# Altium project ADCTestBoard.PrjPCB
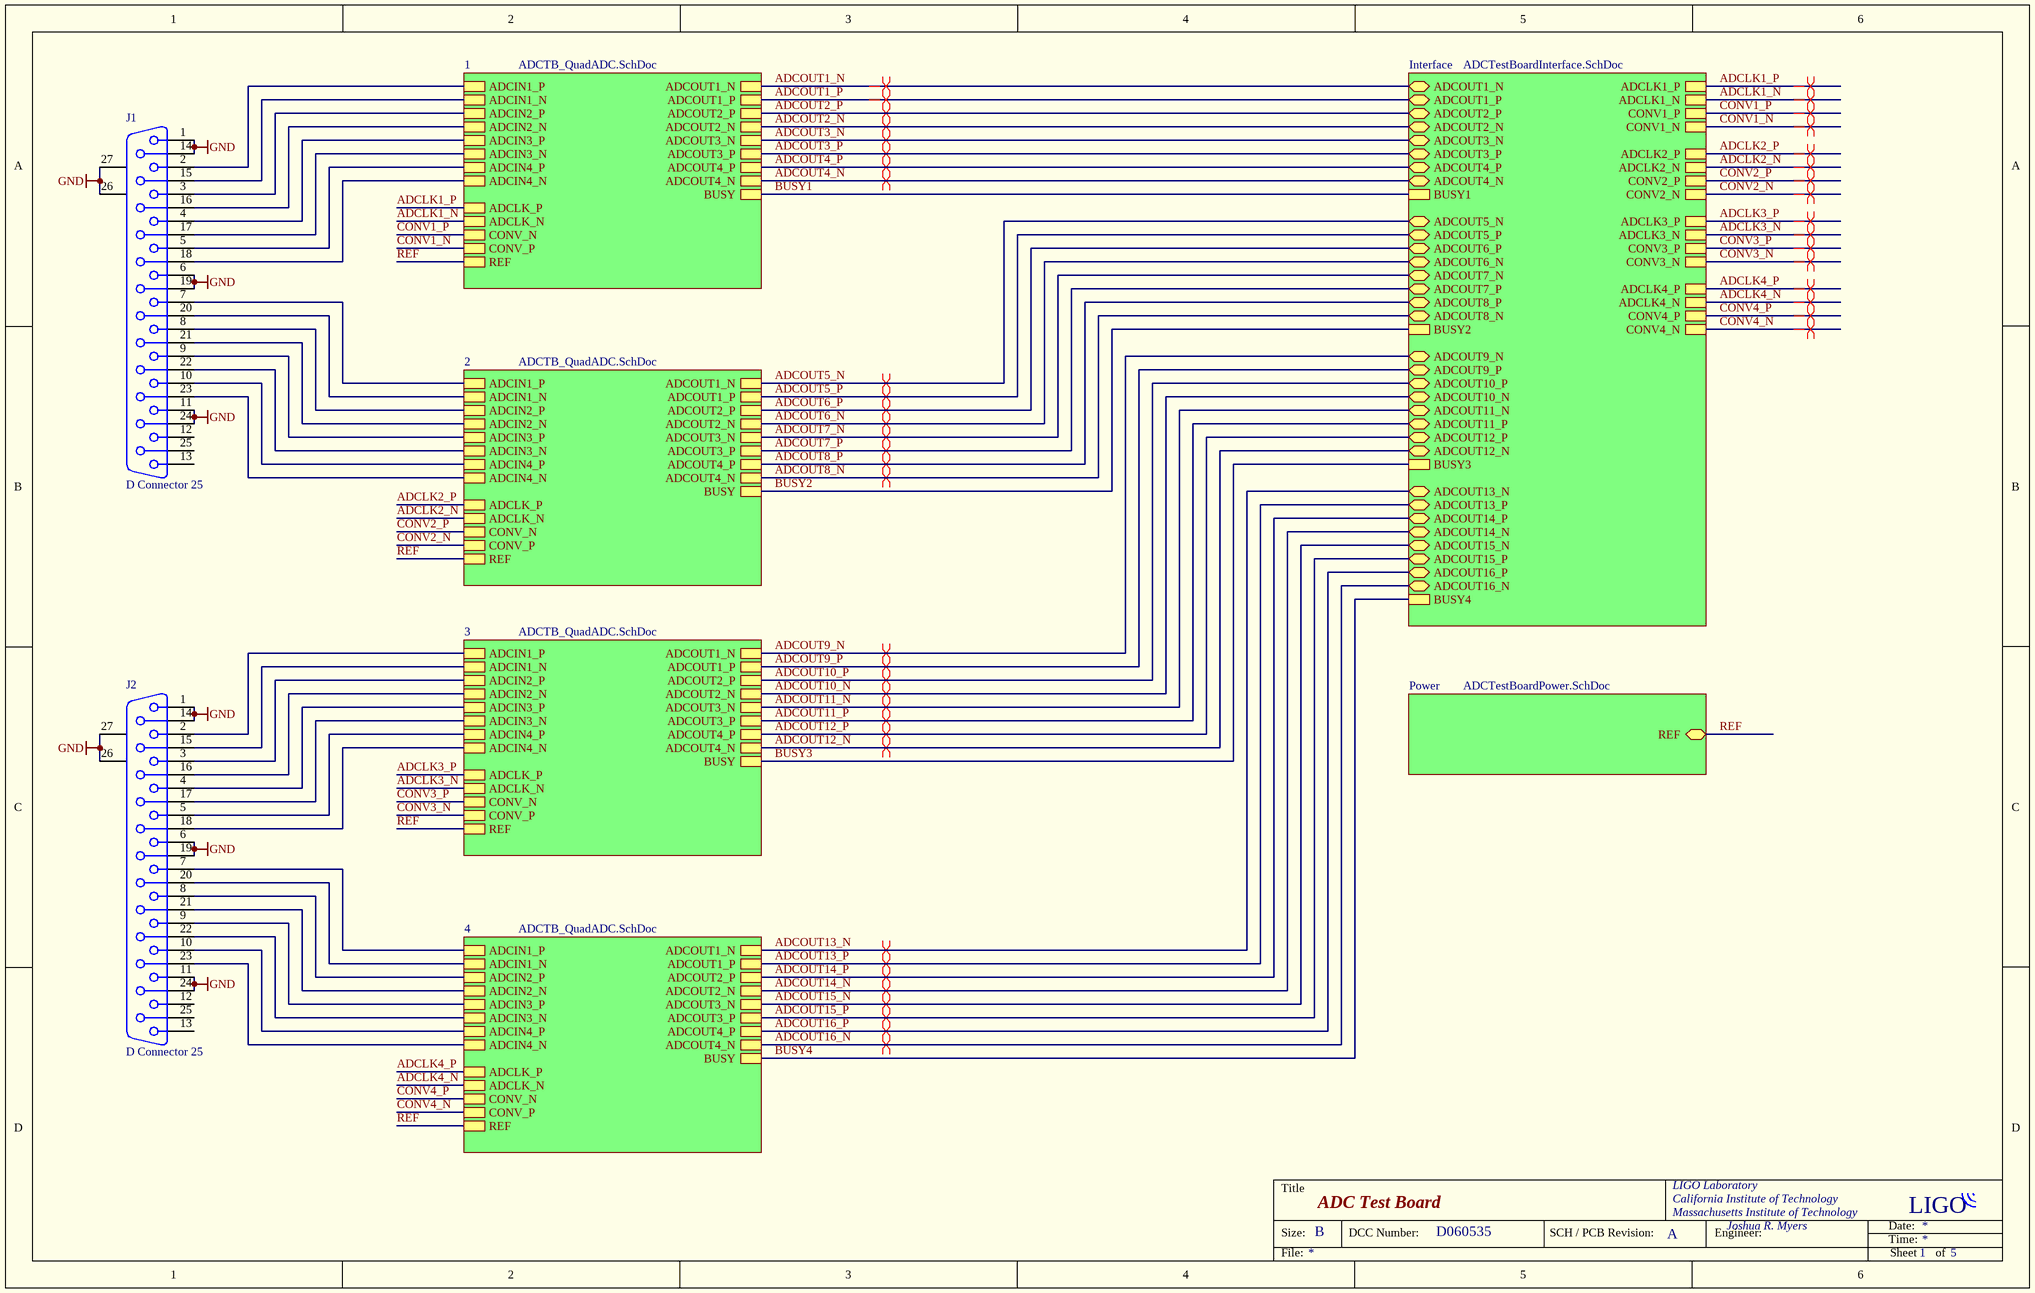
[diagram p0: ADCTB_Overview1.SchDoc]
5 sheets, 1282 parts. Net scope: hierarchical (ports join the sheet entries above them; power ports are global).
Board file: ADCTestBoard.PcbDoc
Sheets:
  ADCTB_Overview1.SchDoc
    1 = ADCTB_QuadADC.SchDoc
      1 = ADCTB_Converter.SchDoc
      2 = ADCTB_Converter.SchDoc
      3 = ADCTB_Converter.SchDoc
      4 = ADCTB_Converter.SchDoc
    2 = ADCTB_QuadADC.SchDoc
      1 = ADCTB_Converter.SchDoc
      2 = ADCTB_Converter.SchDoc
      3 = ADCTB_Converter.SchDoc
      4 = ADCTB_Converter.SchDoc
    3 = ADCTB_QuadADC.SchDoc
      1 = ADCTB_Converter.SchDoc
      2 = ADCTB_Converter.SchDoc
      3 = ADCTB_Converter.SchDoc
      4 = ADCTB_Converter.SchDoc
    Interface = ADCTestBoardInterface.SchDoc
    Power = ADCTestBoardPower.SchDoc
    4 = ADCTB_QuadADC.SchDoc
      1 = ADCTB_Converter.SchDoc
      2 = ADCTB_Converter.SchDoc
      3 = ADCTB_Converter.SchDoc
      4 = ADCTB_Converter.SchDoc

## Sheet ADCTB_Overview1.SchDoc: ADC Test Board
size B; Organization: LIGO Laboratory; Address1: California Institute of Technology; Address2: Massachusetts Institute of Technology; Address3: Joshua R. Myers; DocumentNumber: D060535; Revision: A; SheetNumber: 1; SheetTotal: 5; Engineer: Joshua R. Myers; PageSetup: Record=PageOptions|CenterHorizontal=True|CenterVertical=True|PrintScale=0.70|XCorrection=1.00|YCorrection=1.00|PrintKind=2|BorderSize=5000000|LeftOffset=0|BottomOffset=0|Orientation=2|PaperLength=1000|PaperWidth=1000|Scale=100|PaperSource=15|PrintQuality=1200|MediaType=1|DitherType=10|PaperKind=11 x 17|PrintScaleMode=1

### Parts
J1  D Connector 25  [DB25RA/M]
J2  D Connector 25  [DB25RA/M]

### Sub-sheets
1 = ADCTB_QuadADC.SchDoc: ADCOUT2_N, ADCOUT2_P, ADCOUT1_P, ADCOUT3_N, ADCOUT3_P, ADCOUT4_P, ADCOUT4_N, ADCOUT1_N, ADCIN2_N, ADCIN2_P, ADCIN1_P, ADCIN3_N, ADCIN3_P, ADCIN4_P, ADCIN4_N, ADCIN1_N, BUSY, ADCLK_P, CONV_P, CONV_N, ADCLK_N, REF
2 = ADCTB_QuadADC.SchDoc: ADCOUT2_N, ADCOUT2_P, ADCOUT1_P, ADCOUT3_N, ADCOUT3_P, ADCOUT4_P, ADCOUT4_N, ADCOUT1_N, ADCIN2_N, ADCIN2_P, ADCIN1_P, ADCIN3_N, ADCIN3_P, ADCIN4_P, ADCIN4_N, ADCIN1_N, BUSY, ADCLK_P, CONV_P, CONV_N, ADCLK_N, REF
3 = ADCTB_QuadADC.SchDoc: ADCOUT2_N, ADCOUT2_P, ADCOUT1_P, ADCOUT3_N, ADCOUT3_P, ADCOUT4_P, ADCOUT4_N, ADCOUT1_N, ADCIN2_N, ADCIN2_P, ADCIN1_P, ADCIN3_N, ADCIN3_P, ADCIN4_P, ADCIN4_N, ADCIN1_N, BUSY, ADCLK_P, CONV_P, CONV_N, ADCLK_N, REF
4 = ADCTB_QuadADC.SchDoc: ADCOUT2_N, ADCOUT2_P, ADCOUT1_P, ADCOUT3_N, ADCOUT3_P, ADCOUT4_P, ADCOUT4_N, ADCOUT1_N, ADCIN2_N, ADCIN2_P, ADCIN1_P, ADCIN3_N, ADCIN3_P, ADCIN4_P, ADCIN4_N, ADCIN1_N, BUSY, ADCLK_P, CONV_P, CONV_N, ADCLK_N, REF
Interface = ADCTestBoardInterface.SchDoc: BUSY1, BUSY2, BUSY3, BUSY4, ADCLK2_P, ADCLK1_N, ADCLK1_P, CONV1_P, CONV1_N, CONV4_N, ADCLK4_P, ADCLK4_N, CONV3_N, CONV3_P, CONV4_P, CONV2_P, ADCLK3_P, ADCLK3_N, CONV2_N, ADCLK2_N, ADCOUT13_N, ADCOUT12_P, ADCOUT10_N, ADCOUT7_P, ADCOUT10_P, ADCOUT8_P, ADCOUT5_N, ADCOUT1_N, ADCOUT16_P, ADCOUT9_N, ADCOUT1_P, ADCOUT14_P, ADCOUT4_P, ADCOUT6_N, ADCOUT9_P, ADCOUT7_N, ADCOUT15_N, ADCOUT8_N, ADCOUT15_P, ADCOUT13_P, ADCOUT6_P, ADCOUT11_P, ADCOUT2_N, ADCOUT16_N, ADCOUT4_N, ADCOUT3_N, ADCOUT2_P, ADCOUT5_P, ADCOUT12_N, ADCOUT3_P, ADCOUT11_N, ADCOUT14_N
Power = ADCTestBoardPower.SchDoc: REF

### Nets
GND: J1.1 J1.6 J1.11 J1.14 J1.19 J1.24 J1.26(MH1) J1.27(MH2) J2.1 J2.6 J2.11 J2.14 J2.19 J2.24 J2.26 J2.27
ADCLK1_N: sheet 1/ADCLK_N, sheet Interface/ADCLK1_N
ADCLK1_P: sheet 1/ADCLK_P, sheet Interface/ADCLK1_P
ADCLK2_N: sheet 2/ADCLK_N, sheet Interface/ADCLK2_N
ADCLK2_P: sheet 2/ADCLK_P, sheet Interface/ADCLK2_P
ADCLK3_N: sheet 3/ADCLK_N, sheet Interface/ADCLK3_N
ADCLK3_P: sheet 3/ADCLK_P, sheet Interface/ADCLK3_P
ADCLK4_N: sheet Interface/ADCLK4_N, sheet 4/ADCLK_N
ADCLK4_P: sheet Interface/ADCLK4_P, sheet 4/ADCLK_P
ADCOUT1_N: sheet 1/ADCOUT1_N, sheet Interface/ADCOUT1_N
ADCOUT1_P: sheet 1/ADCOUT1_P, sheet Interface/ADCOUT1_P
ADCOUT2_N: sheet 1/ADCOUT2_N, sheet Interface/ADCOUT2_N
ADCOUT2_P: sheet 1/ADCOUT2_P, sheet Interface/ADCOUT2_P
ADCOUT3_N: sheet 1/ADCOUT3_N, sheet Interface/ADCOUT3_N
ADCOUT3_P: sheet 1/ADCOUT3_P, sheet Interface/ADCOUT3_P
ADCOUT4_N: sheet 1/ADCOUT4_N, sheet Interface/ADCOUT4_N
ADCOUT4_P: sheet 1/ADCOUT4_P, sheet Interface/ADCOUT4_P
ADCOUT5_N: sheet 2/ADCOUT1_N, sheet Interface/ADCOUT5_N
ADCOUT5_P: sheet 2/ADCOUT1_P, sheet Interface/ADCOUT5_P
ADCOUT6_N: sheet 2/ADCOUT2_N, sheet Interface/ADCOUT6_N
ADCOUT6_P: sheet 2/ADCOUT2_P, sheet Interface/ADCOUT6_P
ADCOUT7_N: sheet 2/ADCOUT3_N, sheet Interface/ADCOUT7_N
ADCOUT7_P: sheet 2/ADCOUT3_P, sheet Interface/ADCOUT7_P
ADCOUT8_N: sheet 2/ADCOUT4_N, sheet Interface/ADCOUT8_N
ADCOUT8_P: sheet 2/ADCOUT4_P, sheet Interface/ADCOUT8_P
ADCOUT9_N: sheet 3/ADCOUT1_N, sheet Interface/ADCOUT9_N
ADCOUT9_P: sheet 3/ADCOUT1_P, sheet Interface/ADCOUT9_P
ADCOUT10_N: sheet 3/ADCOUT2_N, sheet Interface/ADCOUT10_N
ADCOUT10_P: sheet 3/ADCOUT2_P, sheet Interface/ADCOUT10_P
ADCOUT11_N: sheet 3/ADCOUT3_N, sheet Interface/ADCOUT11_N
ADCOUT11_P: sheet 3/ADCOUT3_P, sheet Interface/ADCOUT11_P
ADCOUT12_N: sheet 3/ADCOUT4_N, sheet Interface/ADCOUT12_N
ADCOUT12_P: sheet 3/ADCOUT4_P, sheet Interface/ADCOUT12_P
ADCOUT13_N: sheet Interface/ADCOUT13_N, sheet 4/ADCOUT1_N
ADCOUT13_P: sheet Interface/ADCOUT13_P, sheet 4/ADCOUT1_P
ADCOUT14_N: sheet Interface/ADCOUT14_N, sheet 4/ADCOUT2_N
ADCOUT14_P: sheet Interface/ADCOUT14_P, sheet 4/ADCOUT2_P
ADCOUT15_N: sheet Interface/ADCOUT15_N, sheet 4/ADCOUT3_N
ADCOUT15_P: sheet Interface/ADCOUT15_P, sheet 4/ADCOUT3_P
ADCOUT16_N: sheet Interface/ADCOUT16_N, sheet 4/ADCOUT4_N
ADCOUT16_P: sheet Interface/ADCOUT16_P, sheet 4/ADCOUT4_P
BUSY1: sheet 1/BUSY, sheet Interface/BUSY1
BUSY2: sheet 2/BUSY, sheet Interface/BUSY2
BUSY3: sheet 3/BUSY, sheet Interface/BUSY3
BUSY4: sheet Interface/BUSY4, sheet 4/BUSY
CONV1_N: sheet 1/CONV_P, sheet Interface/CONV1_N
CONV1_P: sheet 1/CONV_N, sheet Interface/CONV1_P
CONV2_N: sheet 2/CONV_P, sheet Interface/CONV2_N
CONV2_P: sheet 2/CONV_N, sheet Interface/CONV2_P
CONV3_N: sheet 3/CONV_P, sheet Interface/CONV3_N
CONV3_P: sheet 3/CONV_N, sheet Interface/CONV3_P
CONV4_N: sheet Interface/CONV4_N, sheet 4/CONV_P
CONV4_P: sheet Interface/CONV4_P, sheet 4/CONV_N
REF: sheet 1/REF, sheet 2/REF, sheet 3/REF, sheet Power/REF, sheet 4/REF
NetJ1_2: J1.2 ; sheet 1/ADCIN1_P
NetJ1_3: J1.3 ; sheet 1/ADCIN2_P
NetJ1_4: J1.4 ; sheet 1/ADCIN3_P
NetJ1_5: J1.5 ; sheet 1/ADCIN4_P
NetJ1_7: J1.7 ; sheet 2/ADCIN1_P
NetJ1_8: J1.8 ; sheet 2/ADCIN2_P
NetJ1_9: J1.9 ; sheet 2/ADCIN3_P
NetJ1_10: J1.10 ; sheet 2/ADCIN4_P
NetJ1_15: J1.15 ; sheet 1/ADCIN1_N
NetJ1_16: J1.16 ; sheet 1/ADCIN2_N
NetJ1_17: J1.17 ; sheet 1/ADCIN3_N
NetJ1_18: J1.18 ; sheet 1/ADCIN4_N
NetJ1_20: J1.20 ; sheet 2/ADCIN1_N
NetJ1_21: J1.21 ; sheet 2/ADCIN2_N
NetJ1_22: J1.22 ; sheet 2/ADCIN3_N
NetJ1_23: J1.23 ; sheet 2/ADCIN4_N
NetJ2_2: J2.2 ; sheet 3/ADCIN1_P
NetJ2_3: J2.3 ; sheet 3/ADCIN2_P
NetJ2_4: J2.4 ; sheet 3/ADCIN3_P
NetJ2_5: J2.5 ; sheet 3/ADCIN4_P
NetJ2_7: J2.7 ; sheet 4/ADCIN1_P
NetJ2_8: J2.8 ; sheet 4/ADCIN2_P
NetJ2_9: J2.9 ; sheet 4/ADCIN3_P
NetJ2_10: J2.10 ; sheet 4/ADCIN4_P
NetJ2_15: J2.15 ; sheet 3/ADCIN1_N
NetJ2_16: J2.16 ; sheet 3/ADCIN2_N
NetJ2_17: J2.17 ; sheet 3/ADCIN3_N
NetJ2_18: J2.18 ; sheet 3/ADCIN4_N
NetJ2_20: J2.20 ; sheet 4/ADCIN1_N
NetJ2_21: J2.21 ; sheet 4/ADCIN2_N
NetJ2_22: J2.22 ; sheet 4/ADCIN3_N
NetJ2_23: J2.23 ; sheet 4/ADCIN4_N

Not connected (* = marked no-connect by the designer): J1 12 13 25; J2 12 13 25

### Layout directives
differential pair: ADCLK1_N, ADCLK1_P, ADCLK2_N, ADCLK2_P, ADCLK3_N, ADCLK3_P, ADCLK4_N, ADCLK4_P, ADCOUT1_N, ADCOUT1_P, ADCOUT2_N, ADCOUT2_P, ADCOUT3_N, ADCOUT3_P, ADCOUT4_N, ADCOUT4_P, ADCOUT5_N, ADCOUT5_P, ADCOUT6_N, ADCOUT6_P, ADCOUT7_N, ADCOUT7_P, ADCOUT8_N, ADCOUT8_P, ADCOUT9_N, ADCOUT9_P, ADCOUT10_N, ADCOUT10_P, ADCOUT11_N, ADCOUT11_P, ADCOUT12_N, ADCOUT12_P, ADCOUT13_N, ADCOUT13_P, ADCOUT14_N, ADCOUT14_P, ADCOUT15_N, ADCOUT15_P, ADCOUT16_N, ADCOUT16_P, CONV1_N, CONV1_P, CONV2_N, CONV2_P, CONV3_N, CONV3_P, CONV4_N, CONV4_P

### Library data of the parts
J1 J2 = D Connector 25: Receptacle Assembly, 25 Position, Right Angle; pin to pad: 26>0 27>0; Part Number: 609-1505-ND; Package Information: Latest Revision: U; Positions: 25

## Sheet ADCTB_QuadADC.SchDoc: ADC Test Board: Quad ADC
size B; Organization: LIGO Laboratory; Address1: California Institute of Technology; Address2: Massachusetts Institute of Technology; Address3: Joshua R. Myers; DocumentNumber: D060535; Revision: A; SheetNumber: 2; SheetTotal: 5; Engineer: Joshua R. Myers
Used 4 times, as channels 1, 2, 3, 4. Parts and nets are listed once, with the designators drawn on the sheet.
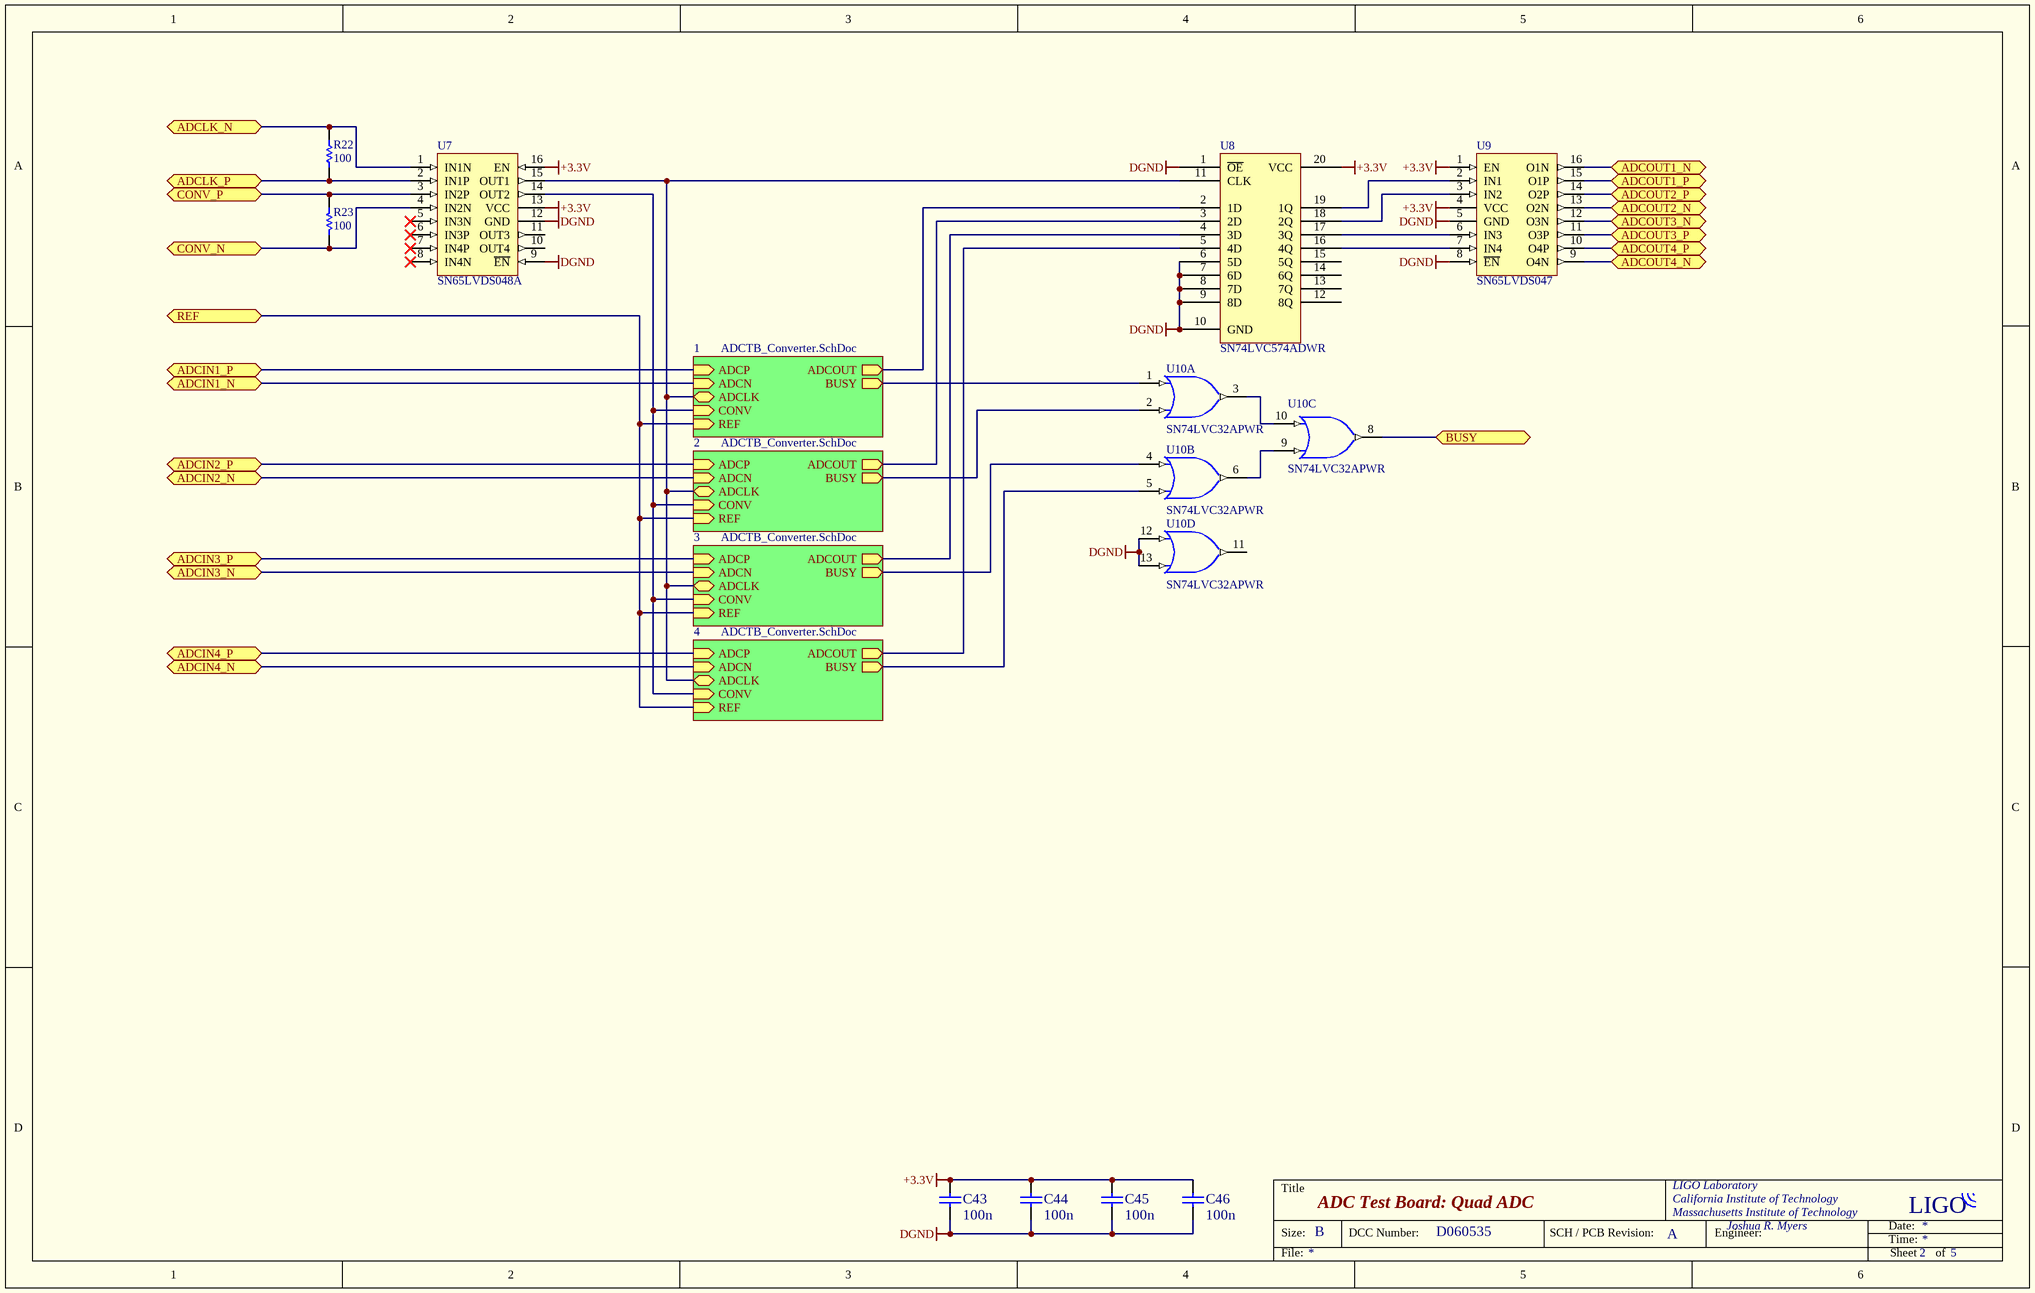
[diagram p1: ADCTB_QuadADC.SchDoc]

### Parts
C43  100n  [CC2013-0805]
C44  100n  [CC2013-0805]
C45  100n  [CC2013-0805]
C46  100n  [CC2013-0805]
R22  100  [CR2012-0805]
R23  100  [CR2012-0805]
U7  SN65LVDS048A  [SO-G16]
U8  SN74LVC574ADWR  [DW020_N]
U9  SN65LVDS047  [SO-G16]
U10  SN74LVC32APWR  [PW014]  (parts A,B,C,D of 4)

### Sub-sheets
1 = ADCTB_Converter.SchDoc: ADCOUT (out), ADCLK (bidir), BUSY (out), CONV (in), REF (in), ADCP (in), ADCN (in)
2 = ADCTB_Converter.SchDoc: ADCOUT (out), ADCLK (bidir), BUSY (out), CONV (in), REF (in), ADCP (in), ADCN (in)
3 = ADCTB_Converter.SchDoc: ADCOUT (out), ADCLK (bidir), BUSY (out), CONV (in), REF (in), ADCP (in), ADCN (in)
4 = ADCTB_Converter.SchDoc: ADCOUT (out), ADCLK (bidir), BUSY (out), CONV (in), REF (in), ADCP (in), ADCN (in)

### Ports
ADCIN1_N, ADCIN1_P, ADCIN2_N, ADCIN2_P, ADCIN3_N, ADCIN3_P, ADCIN4_N, ADCIN4_P, ADCLK_N, ADCLK_P, ADCOUT1_N, ADCOUT1_P, ADCOUT2_N, ADCOUT2_P, ADCOUT3_N, ADCOUT3_P, ADCOUT4_N, ADCOUT4_P, BUSY, CONV_N, CONV_P, REF

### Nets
+3.3V: C43.1 C44.1 C45.1 C46.1 U7.13(VCC) U7.16(EN) U8.20(VCC) U9.1(EN) U9.4(VCC) U10.14(+3.3V)
DGND: C43.2 C44.2 C45.2 C46.2 U7.9(~{EN}) U7.12(GND) U8.1(~{OE}) U8.6(5D) U8.7(6D) U8.8(7D) U8.9(8D) U8.10(GND) U9.5(GND) U9.8(~{EN}) U10.7(DGND) U10.12(A) U10.13(B)
ADCIN1_N: port ADCIN1_N, sheet 1/ADCN
ADCIN1_P: port ADCIN1_P, sheet 1/ADCP
ADCIN2_N: port ADCIN2_N, sheet 2/ADCN
ADCIN2_P: port ADCIN2_P, sheet 2/ADCP
ADCIN3_N: port ADCIN3_N, sheet 3/ADCN
ADCIN3_P: port ADCIN3_P, sheet 3/ADCP
ADCIN4_N: port ADCIN4_N, sheet 4/ADCN
ADCIN4_P: port ADCIN4_P, sheet 4/ADCP
ADCLK_N: R22.1 U7.1(IN1N) ; port ADCLK_N
ADCLK_P: R22.2 U7.2(IN1P) ; port ADCLK_P
ADCOUT1_N: U9.16(O1N) ; port ADCOUT1_N
ADCOUT1_P: U9.15(O1P) ; port ADCOUT1_P
ADCOUT2_N: U9.13(O2N) ; port ADCOUT2_N
ADCOUT2_P: U9.14(O2P) ; port ADCOUT2_P
ADCOUT3_N: U9.12(O3N) ; port ADCOUT3_N
ADCOUT3_P: U9.11(O3P) ; port ADCOUT3_P
ADCOUT4_N: U9.9(O4N) ; port ADCOUT4_N
ADCOUT4_P: U9.10(O4P) ; port ADCOUT4_P
BUSY: U10.8(Y) ; port BUSY
CONV_N: R23.1 U7.4(IN2N) ; port CONV_N
CONV_P: R23.2 U7.3(IN2P) ; port CONV_P
REF: port REF, sheet 1/REF, sheet 2/REF, sheet 3/REF, sheet 4/REF
NetU7_14: U7.14(OUT2) ; sheet 1/CONV, sheet 2/CONV, sheet 3/CONV, sheet 4/CONV
NetU7_15: U7.15(OUT1) U8.11(CLK) ; sheet 1/ADCLK, sheet 2/ADCLK, sheet 3/ADCLK, sheet 4/ADCLK
NetU8_2: U8.2(1D) ; sheet 1/ADCOUT
NetU8_3: U8.3(2D) ; sheet 2/ADCOUT
NetU8_4: U8.4(3D) ; sheet 3/ADCOUT
NetU8_5: U8.5(4D) ; sheet 4/ADCOUT
NetU8_16: U8.16(4Q) U9.7(IN4)
NetU8_17: U8.17(3Q) U9.6(IN3)
NetU8_18: U8.18(2Q) U9.3(IN2)
NetU8_19: U8.19(1Q) U9.2(IN1)
NetU10_1: U10.1(A) ; sheet 1/BUSY
NetU10_2: U10.2(B) ; sheet 2/BUSY
NetU10_3: U10.3(Y) U10.10(B)
NetU10_4: U10.4(A) ; sheet 3/BUSY
NetU10_5: U10.5(B) ; sheet 4/BUSY
NetU10_6: U10.6(Y) U10.9(A)

Not connected (* = marked no-connect by the designer): U7 5(IN3N)* 6(IN3P)* 7(IN4P)* 8(IN4N)* 10(OUT4) 11(OUT3); U8 12(8Q) 13(7Q) 14(6Q) 15(5Q); U10 11(Y)

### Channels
1: designators end in _1; ports ADCIN1_N=NetJ1_15 ADCIN1_P=NetJ1_2 ADCIN2_N=NetJ1_16 ADCIN2_P=NetJ1_3 ADCIN3_N=NetJ1_17 ADCIN3_P=NetJ1_4 ADCIN4_N=NetJ1_18 ADCIN4_P=NetJ1_5 ADCLK_N=ADCLK1_N ADCLK_P=ADCLK1_P ADCOUT1_N=ADCOUT1_N ADCOUT1_P=ADCOUT1_P ADCOUT2_N=ADCOUT2_N ADCOUT2_P=ADCOUT2_P ADCOUT3_N=ADCOUT3_N ADCOUT3_P=ADCOUT3_P ADCOUT4_N=ADCOUT4_N ADCOUT4_P=ADCOUT4_P BUSY=BUSY1 CONV_N=CONV1_P CONV_P=CONV1_N REF=REF
2: designators end in _2; ports ADCIN1_N=NetJ1_20 ADCIN1_P=NetJ1_7 ADCIN2_N=NetJ1_21 ADCIN2_P=NetJ1_8 ADCIN3_N=NetJ1_22 ADCIN3_P=NetJ1_9 ADCIN4_N=NetJ1_23 ADCIN4_P=NetJ1_10 ADCLK_N=ADCLK2_N ADCLK_P=ADCLK2_P ADCOUT1_N=ADCOUT5_N ADCOUT1_P=ADCOUT5_P ADCOUT2_N=ADCOUT6_N ADCOUT2_P=ADCOUT6_P ADCOUT3_N=ADCOUT7_N ADCOUT3_P=ADCOUT7_P ADCOUT4_N=ADCOUT8_N ADCOUT4_P=ADCOUT8_P BUSY=BUSY2 CONV_N=CONV2_P CONV_P=CONV2_N REF=REF
3: designators end in _3; ports ADCIN1_N=NetJ2_15 ADCIN1_P=NetJ2_2 ADCIN2_N=NetJ2_16 ADCIN2_P=NetJ2_3 ADCIN3_N=NetJ2_17 ADCIN3_P=NetJ2_4 ADCIN4_N=NetJ2_18 ADCIN4_P=NetJ2_5 ADCLK_N=ADCLK3_N ADCLK_P=ADCLK3_P ADCOUT1_N=ADCOUT9_N ADCOUT1_P=ADCOUT9_P ADCOUT2_N=ADCOUT10_N ADCOUT2_P=ADCOUT10_P ADCOUT3_N=ADCOUT11_N ADCOUT3_P=ADCOUT11_P ADCOUT4_N=ADCOUT12_N ADCOUT4_P=ADCOUT12_P BUSY=BUSY3 CONV_N=CONV3_P CONV_P=CONV3_N REF=REF
4: designators end in _4; ports ADCIN1_N=NetJ2_20 ADCIN1_P=NetJ2_7 ADCIN2_N=NetJ2_21 ADCIN2_P=NetJ2_8 ADCIN3_N=NetJ2_22 ADCIN3_P=NetJ2_9 ADCIN4_N=NetJ2_23 ADCIN4_P=NetJ2_10 ADCLK_N=ADCLK4_N ADCLK_P=ADCLK4_P ADCOUT1_N=ADCOUT13_N ADCOUT1_P=ADCOUT13_P ADCOUT2_N=ADCOUT14_N ADCOUT2_P=ADCOUT14_P ADCOUT3_N=ADCOUT15_N ADCOUT3_P=ADCOUT15_P ADCOUT4_N=ADCOUT16_N ADCOUT4_P=ADCOUT16_P BUSY=BUSY4 CONV_N=CONV4_P CONV_P=CONV4_N REF=REF

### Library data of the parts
C43-C46 = Cap Semi: Capacitor (Semiconductor SIM Model); Part Number: 478-1395-1-ND
R22 R23 = Res1: Resistor; Part Number: 311-100CRCT-ND; Tolerance: 1%
U7 = SN65LVDS048: LVDS RCVR; Part Number: 296-6911-5-ND
U8 = SN74LVC574SC: Octal D type flip-flop; Part Number: 296-8531-5-ND
U9 = SN65LVDS047: LVDS DRIVER; Part Number: 296-6909-5-ND
U10 = SN74LVC32AD: Quadruple 2-Input Positive-OR Gate; Part Number: 296-1236-1-ND

## Sheet ADCTB_Converter.SchDoc: ADC Test Board: Front End
size B; Organization: LIGO Laboratory; Address1: California Institute of Technology; Address2: Massachusetts Institute of Technology; Address3: Joshua R. Myers; DocumentNumber: D060535; Revision: A; SheetNumber: 3; SheetTotal: 5; Engineer: Joshua R. Myers; PageSetup: Record=PageOptions|CenterHorizontal=True|CenterVertical=True|PrintScale=1.12|XCorrection=1.00|YCorrection=1.00|PrintKind=2|BorderSize=5000000|LeftOffset=0|BottomOffset=0|Orientation=2|PaperLength=1000|PaperWidth=1000|Scale=100|PaperSource=7|PrintQuality=-4|MediaType=1|DitherType=10|PaperKind=Tabloid|PrintScaleMode=1
Used 16 times, as channels 1/1, 1/2, 1/3, 1/4, 2/1, 2/2, 2/3, 2/4, 3/1, 3/2, 3/3, 3/4, 4/1, 4/2, 4/3, 4/4. Parts and nets are listed once, with the designators drawn on the sheet.
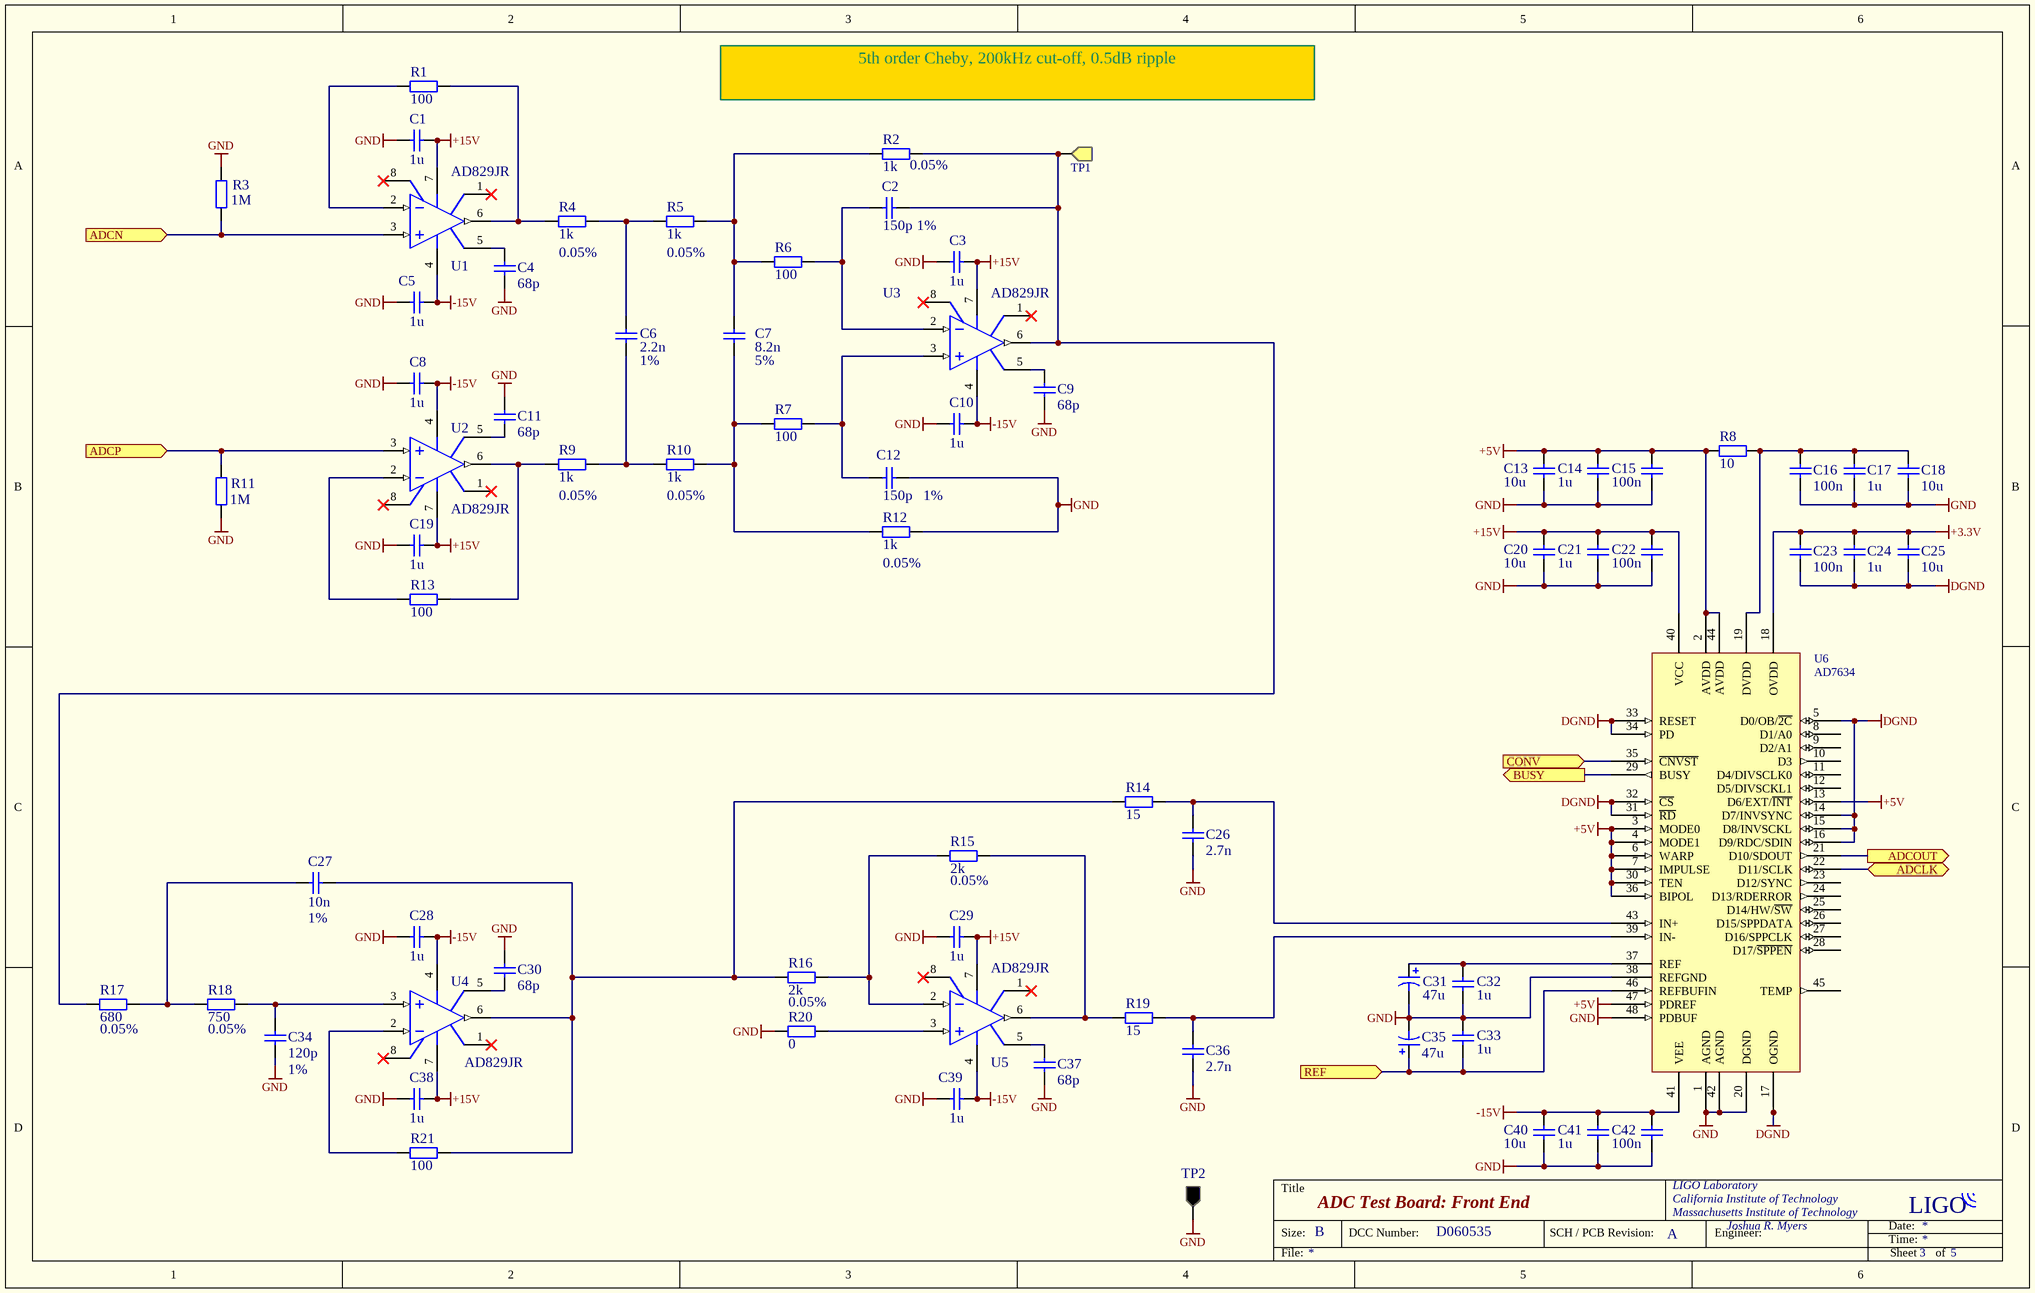
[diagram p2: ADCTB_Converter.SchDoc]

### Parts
C1  1u  [CC2013-0805]
C2  Tolerance: 1%  [CC2013-0805]  (hidden comment: 150p)
C3  1u  [CC2013-0805]
C4  68p  [CC2013-0805]
C5  1u  [CC2013-0805]
C6  Tolerance: 1%  [CC3216-1206]  (hidden comment: 2.2n)
C7  Tolerance: 5%  [CC3216-1206]  (hidden comment: 8.2n)
C8  1u  [CC2013-0805]
C9  68p  [CC2013-0805]
C10  1u  [CC2013-0805]
C11  68p  [CC2013-0805]
C12  Tolerance: 1%  [CC2013-0805]  (hidden comment: 150p)
C13  10u  [CC3216-1206]
C14  1u  [CC2013-0805]
C15  100n  [CC2013-0805]
C16  100n  [CC2013-0805]
C17  1u  [CC2013-0805]
C18  10u  [CC3216-1206]
C19  1u  [CC2013-0805]
C20  10u  [CC3216-1206]
C21  1u  [CC2013-0805]
C22  100n  [CC2013-0805]
C23  100n  [CC2013-0805]
C24  1u  [CC2013-0805]
C25  10u  [CC3216-1206]
C26  2.7n  [CC2013-0805]
C27  Tolerance: 1%  [CC3216-1206]  (hidden comment: 10n)
C28  1u  [CC2013-0805]
C29  1u  [CC2013-0805]
C30  68p  [CC2013-0805]
C31  47u  [CC3225-1210]
C32  1u  [CC2013-0805]
C33  1u  [CC2013-0805]
C34  Tolerance: 1%  [CC2013-0805]  (hidden comment: 120p)
C35  47u  [CC3225-1210]
C36  2.7n  [CC2013-0805]
C37  68p  [CC2013-0805]
C38  1u  [CC2013-0805]
C39  1u  [CC2013-0805]
C40  10u  [CC3216-1206]
C41  1u  [CC2013-0805]
C42  100n  [CC2013-0805]
R1  100  [CR2012-0805]
R2  Tolerance: 0.05%  [CR2012-0805]  (hidden comment: 1k)
R3  1M  [CR2012-0805]
R4  Tolerance: 0.05%  [CR2012-0805]  (hidden comment: 1k)
R5  Tolerance: 0.05%  [CR2012-0805]  (hidden comment: 1k)
R6  100  [CR2012-0805]
R7  100  [CR2012-0805]
R8  10  [CR2012-0805]
R9  Tolerance: 0.05%  [CR2012-0805]  (hidden comment: 1k)
R10  Tolerance: 0.05%  [CR2012-0805]  (hidden comment: 1k)
R11  1M  [CR2012-0805]
R12  Tolerance: 0.05%  [CR2012-0805]  (hidden comment: 1k)
R13  100  [CR2012-0805]
R14  15  [CR2012-0805]
R15  Tolerance: 0.05%  [CR2012-0805]  (hidden comment: 2k)
R16  Tolerance: 0.05%  [CR2012-0805]  (hidden comment: 2k)
R17  Tolerance: 0.05%  [CR2012-0805]  (hidden comment: 680)
R18  Tolerance: 0.05%  [CR2012-0805]  (hidden comment: 750)
R19  15  [CR2012-0805]
R20  0  [CR2012-0805]
R21  100  [CR2012-0805]
TP1  Testpoint  [TP1]  (value not drawn)
TP2  Testpoint  [TP1]  (value not drawn)
U1  AD829JR  [R-8D_N]
U2  AD829JR  [R-8D_N]
U3  AD829JR  [R-8D_N]
U4  AD829JR  [R-8D_N]
U5  AD829JR  [R-8D_N]
U6  AD7634  [LFCSP_VQ48]

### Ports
ADCLK (bidir), ADCN (in), ADCOUT (out), ADCP (in), BUSY (out), CONV (in), REF (in)

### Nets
+3.3V: C23.2 C24.2 C25.2 U6.18(OVDD)
+5V: C13.2 C14.2 C15.2 R8.2 U6.2(AVDD) U6.3(MODE0) U6.4(MODE1) U6.6(WARP) U6.7(IMPULSE) U6.13(D6/EXT/~{INT}) U6.30(TEN) U6.36(BIPOL) U6.44(AVDD) U6.47(PDREF)
+15V: C1.1 C3.1 C19.1 C20.2 C21.2 C22.2 C29.1 C38.1 U1.7(V+) U2.7(V+) U3.7(V+) U4.7(V+) U5.7(V+) U6.40(VCC)
-15V: C5.1 C8.1 C10.1 C28.1 C39.1 C40.2 C41.2 C42.2 U1.4(V-) U2.4(V-) U3.4(V-) U4.4(V-) U5.4(V-) U6.41(VEE)
DGND: C23.1 C24.1 C25.1 U6.5(D0/OB/~{2C}) U6.14(D7/INVSYNC) U6.15(D8/INVSCKL) U6.16(D9/RDC/SDIN) U6.17(OGND) U6.31(~{RD}) U6.32(~{CS}) U6.33(RESET) U6.34(PD)
GND: C1.2 C3.2 C4.2 C5.2 C8.2 C9.2 C10.2 C11.2 C12.1 C13.1 C14.1 C15.1 C16.1 C17.1 C18.1 C19.2 C20.1 C21.1 C22.1 C26.2 C28.2 C29.2 C30.2 C31.2 C32.2 C33.1 C34.2 C35.2 C36.2 C37.2 C38.2 C39.2 C40.1 C41.1 C42.1 R3.2 R11.2 R12.2 R20.2 TP2.1 U6.1(AGND) U6.20(DGND) U6.38(REFGND) U6.42(AGND) U6.48(PDBUF)
ADCLK: U6.22(D11/SCLK) ; port ADCLK
ADCN: R3.1 U1.3(IN+) ; port ADCN
ADCOUT: U6.21(D10/SDOUT) ; port ADCOUT
ADCP: R11.1 U2.3(IN+) ; port ADCP
BUSY: U6.29(BUSY) ; port BUSY
CONV: U6.35(~{CNVST}) ; port CONV
REF: C33.2 C35.1 U6.46(REFBUFIN) ; port REF
NetC2_1: C2.1 R2.2 R17.1 TP1.1 U3.6(OUT)
NetC2_2: C2.2 R6.2 U3.2(IN-)
NetC4_1: C4.1 U1.5(C_COMP)
NetC6_1: C6.1 R4.2 R5.1
NetC6_2: C6.2 R9.2 R10.1
NetC7_1: C7.1 R2.1 R5.2 R6.1
NetC7_2: C7.2 R7.1 R10.2 R12.1
NetC9_1: C9.1 U3.5(C_COMP)
NetC11_1: C11.1 U2.5(C_COMP)
NetC12_2: C12.2 R7.2 U3.3(IN+)
NetC16_2: C16.2 C17.2 C18.2 R8.1 U6.19(DVDD)
NetC26_1: C26.1 R14.1 U6.43(IN+)
NetC27_1: C27.1 R14.2 R16.2 R21.2 U4.6(OUT)
NetC27_2: C27.2 R17.2 R18.1
NetC30_1: C30.1 U4.5(C_COMP)
NetC31_1: C31.1 C32.1 U6.37(REF)
NetC34_1: C34.1 R18.2 U4.3(IN+)
NetC36_1: C36.1 R19.1 U6.39(IN-)
NetC37_1: C37.1 U5.5(C_COMP)
NetR1_1: R1.1 U1.2(IN-)
NetR1_2: R1.2 R4.1 U1.6(OUT)
NetR9_1: R9.1 R13.2 U2.6(OUT)
NetR13_1: R13.1 U2.2(IN-)
NetR15_1: R15.1 R19.2 U5.6(OUT)
NetR15_2: R15.2 R16.1 U5.2(IN-)
NetR20_1: R20.1 U5.3(IN+)
NetR21_1: R21.1 U4.2(IN-)

Not connected (* = marked no-connect by the designer): U1 1(OS_NUL)* 8(OS_NUL)*; U2 1(OS_NUL)* 8(OS_NUL)*; U3 1(OS_NUL)* 8(OS_NUL)*; U4 1(OS_NUL)* 8(OS_NUL)*; U5 1(OS_NUL)* 8(OS_NUL)*; U6 8(D1/A0) 9(D2/A1) 10(D3) 11(D4/DIVSCLK0) 12(D5/DIVSCKL1) 23(D12/SYNC) 24(D13/RDERROR) 25(D14/HW/~{SW}) 26(D15/SPPDATA) 27(D16/SPPCLK) 28(D17/~{SPPEN}) 45(TEMP)

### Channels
1/1: designators end in _1; ports ADCLK=NetU6_1_22 ADCN=NetJ1_15 ADCOUT=NetU6_1_21 ADCP=NetJ1_2 BUSY=NetU6_1_29 CONV=NetU6_1_35 REF=REF
1/2: designators end in _2; ports ADCLK=NetU6_1_22 ADCN=NetJ1_16 ADCOUT=NetU6_2_21 ADCP=NetJ1_3 BUSY=NetU6_2_29 CONV=NetU6_1_35 REF=REF
1/3: designators end in _3; ports ADCLK=NetU6_1_22 ADCN=NetJ1_17 ADCOUT=NetU6_3_21 ADCP=NetJ1_4 BUSY=NetU6_3_29 CONV=NetU6_1_35 REF=REF
1/4: designators end in _4; ports ADCLK=NetU6_1_22 ADCN=NetJ1_18 ADCOUT=NetU6_4_21 ADCP=NetJ1_5 BUSY=NetU6_4_29 CONV=NetU6_1_35 REF=REF
2/1: designators end in _5; ports ADCLK=NetU6_5_22 ADCN=NetJ1_20 ADCOUT=NetU6_5_21 ADCP=NetJ1_7 BUSY=NetU6_5_29 CONV=NetU6_5_35 REF=REF
2/2: designators end in _6; ports ADCLK=NetU6_5_22 ADCN=NetJ1_21 ADCOUT=NetU6_6_21 ADCP=NetJ1_8 BUSY=NetU6_6_29 CONV=NetU6_5_35 REF=REF
2/3: designators end in _7; ports ADCLK=NetU6_5_22 ADCN=NetJ1_22 ADCOUT=NetU6_7_21 ADCP=NetJ1_9 BUSY=NetU6_7_29 CONV=NetU6_5_35 REF=REF
2/4: designators end in _8; ports ADCLK=NetU6_5_22 ADCN=NetJ1_23 ADCOUT=NetU6_8_21 ADCP=NetJ1_10 BUSY=NetU6_8_29 CONV=NetU6_5_35 REF=REF
3/1: designators end in _9; ports ADCLK=NetU6_9_22 ADCN=NetJ2_15 ADCOUT=NetU6_9_21 ADCP=NetJ2_2 BUSY=NetU6_9_29 CONV=NetU6_9_35 REF=REF
3/2: designators end in _10; ports ADCLK=NetU6_9_22 ADCN=NetJ2_16 ADCOUT=NetU6_10_21 ADCP=NetJ2_3 BUSY=NetU6_10_29 CONV=NetU6_9_35 REF=REF
3/3: designators end in _11; ports ADCLK=NetU6_9_22 ADCN=NetJ2_17 ADCOUT=NetU6_11_21 ADCP=NetJ2_4 BUSY=NetU6_11_29 CONV=NetU6_9_35 REF=REF
3/4: designators end in _12; ports ADCLK=NetU6_9_22 ADCN=NetJ2_18 ADCOUT=NetU6_12_21 ADCP=NetJ2_5 BUSY=NetU6_12_29 CONV=NetU6_9_35 REF=REF
4/1: designators end in _13; ports ADCLK=NetU6_13_22 ADCN=NetJ2_20 ADCOUT=NetU6_13_21 ADCP=NetJ2_7 BUSY=NetU6_13_29 CONV=NetU6_13_35 REF=REF
4/2: designators end in _14; ports ADCLK=NetU6_13_22 ADCN=NetJ2_21 ADCOUT=NetU6_14_21 ADCP=NetJ2_8 BUSY=NetU6_14_29 CONV=NetU6_13_35 REF=REF
4/3: designators end in _15; ports ADCLK=NetU6_13_22 ADCN=NetJ2_22 ADCOUT=NetU6_15_21 ADCP=NetJ2_9 BUSY=NetU6_15_29 CONV=NetU6_13_35 REF=REF
4/4: designators end in _16; ports ADCLK=NetU6_13_22 ADCN=NetJ2_23 ADCOUT=NetU6_16_21 ADCP=NetJ2_10 BUSY=NetU6_16_29 CONV=NetU6_13_35 REF=REF

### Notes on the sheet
- 5th order Cheby, 200kHz cut-off, 0.5dB ripple

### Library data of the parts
C1 C3 C5 C8 C10 C14 C17 C19 C21 C24 C28 C29 C32 C33 C38 C39 C41 = Cap Semi: Capacitor (Semiconductor SIM Model); Part Number: PCC2319CT-ND
C2 C12 = Cap Semi: Capacitor (Semiconductor SIM Model); Part Number: 80-C0805C151F5G
C4 C9 C11 C30 C37 = Cap Semi: Capacitor (Semiconductor SIM Model); Part Number: 311-1109-1-ND
C6 = Cap Semi: Capacitor (Semiconductor SIM Model); Part Number: 581-12065A222F
C7 = Cap Semi: Capacitor (Semiconductor SIM Model); Part Number: PCC2166CT-ND
C13 C18 C20 C25 C40 = Cap Semi: Capacitor (Semiconductor SIM Model); Part Number: PCC2414CT-ND
C15 C16 C22 C23 C42 = Cap Semi: as C43 on sheet ADCTB_QuadADC
C26 C36 = Cap Semi: Capacitor (Semiconductor SIM Model); Part Number: 490-1630-1-ND; Tolerance: 5%
C27 = Cap Semi: Capacitor (Semiconductor SIM Model); Part Number: 581-12063A103G
C31 C35 = T494D: Solid Tantalum Chip Capacitor, Standard T494 Series - Low ESR, Industrial Grade; Part Number: PCC2335CT-ND
C34 = Cap Semi: Capacitor (Semiconductor SIM Model); Part Number: 80-C0805C121F1G
R1 R6 R7 R13 R21 = Res2: Resistor; Part Number: 311-100CRCT-ND; Tolerance: 1%
R2 R4 R5 R9 R10 R12 = Res2: Resistor; Part Number: RG20N1.0KWCT-ND
R3 R11 = Res2: Resistor; Part Number: 311-1.00MCRCT-ND; Tolerance: 1%
R8 = Res2: Resistor; Part Number: 311-10.0CRCT-ND; Tolerance: 5%
R14 R19 = Res2: Resistor; Part Number: 311-15.0CRCT-ND; Tolerance: 1%
R15 R16 = Res2: Resistor; Part Number: RG20N2.0KWCT-ND
R17 = Res2: Resistor; Part Number: RG20N680WCT-ND
R18 = Res2: Resistor; Part Number: RG20N750WCT-ND
R20 = Res2: Resistor; Part Number: 311-0.0ARCT-ND; Tolerance: 1%
TP1 = TP_SIGNAL: Testpoint, yellow; Part Number: 5009K-ND
TP2 = TP_GND: Part Number: 5006K-ND
U1-U5 = AD829JR: High-Speed, Low-Noise Video Operational Amplifier; Part Number: AD829JR-ND; PackageDocument: 1998
U6 = AD7634BST: 18 bit SAR ADC, 670kSPS, 10V bipolar; Part Number: AD7634BCPZ-ND

## Sheet ADCTestBoardInterface.SchDoc: ADC Test Board: Interface
size B; Organization: LIGO Laboratory; Address1: California Institute of Technology; Address2: Massachusetts Institute of Technology; Address3: Joshua R. Myers; DocumentNumber: D060535; Revision: A; SheetNumber: 5; SheetTotal: 5; Engineer: Joshua R. Myers
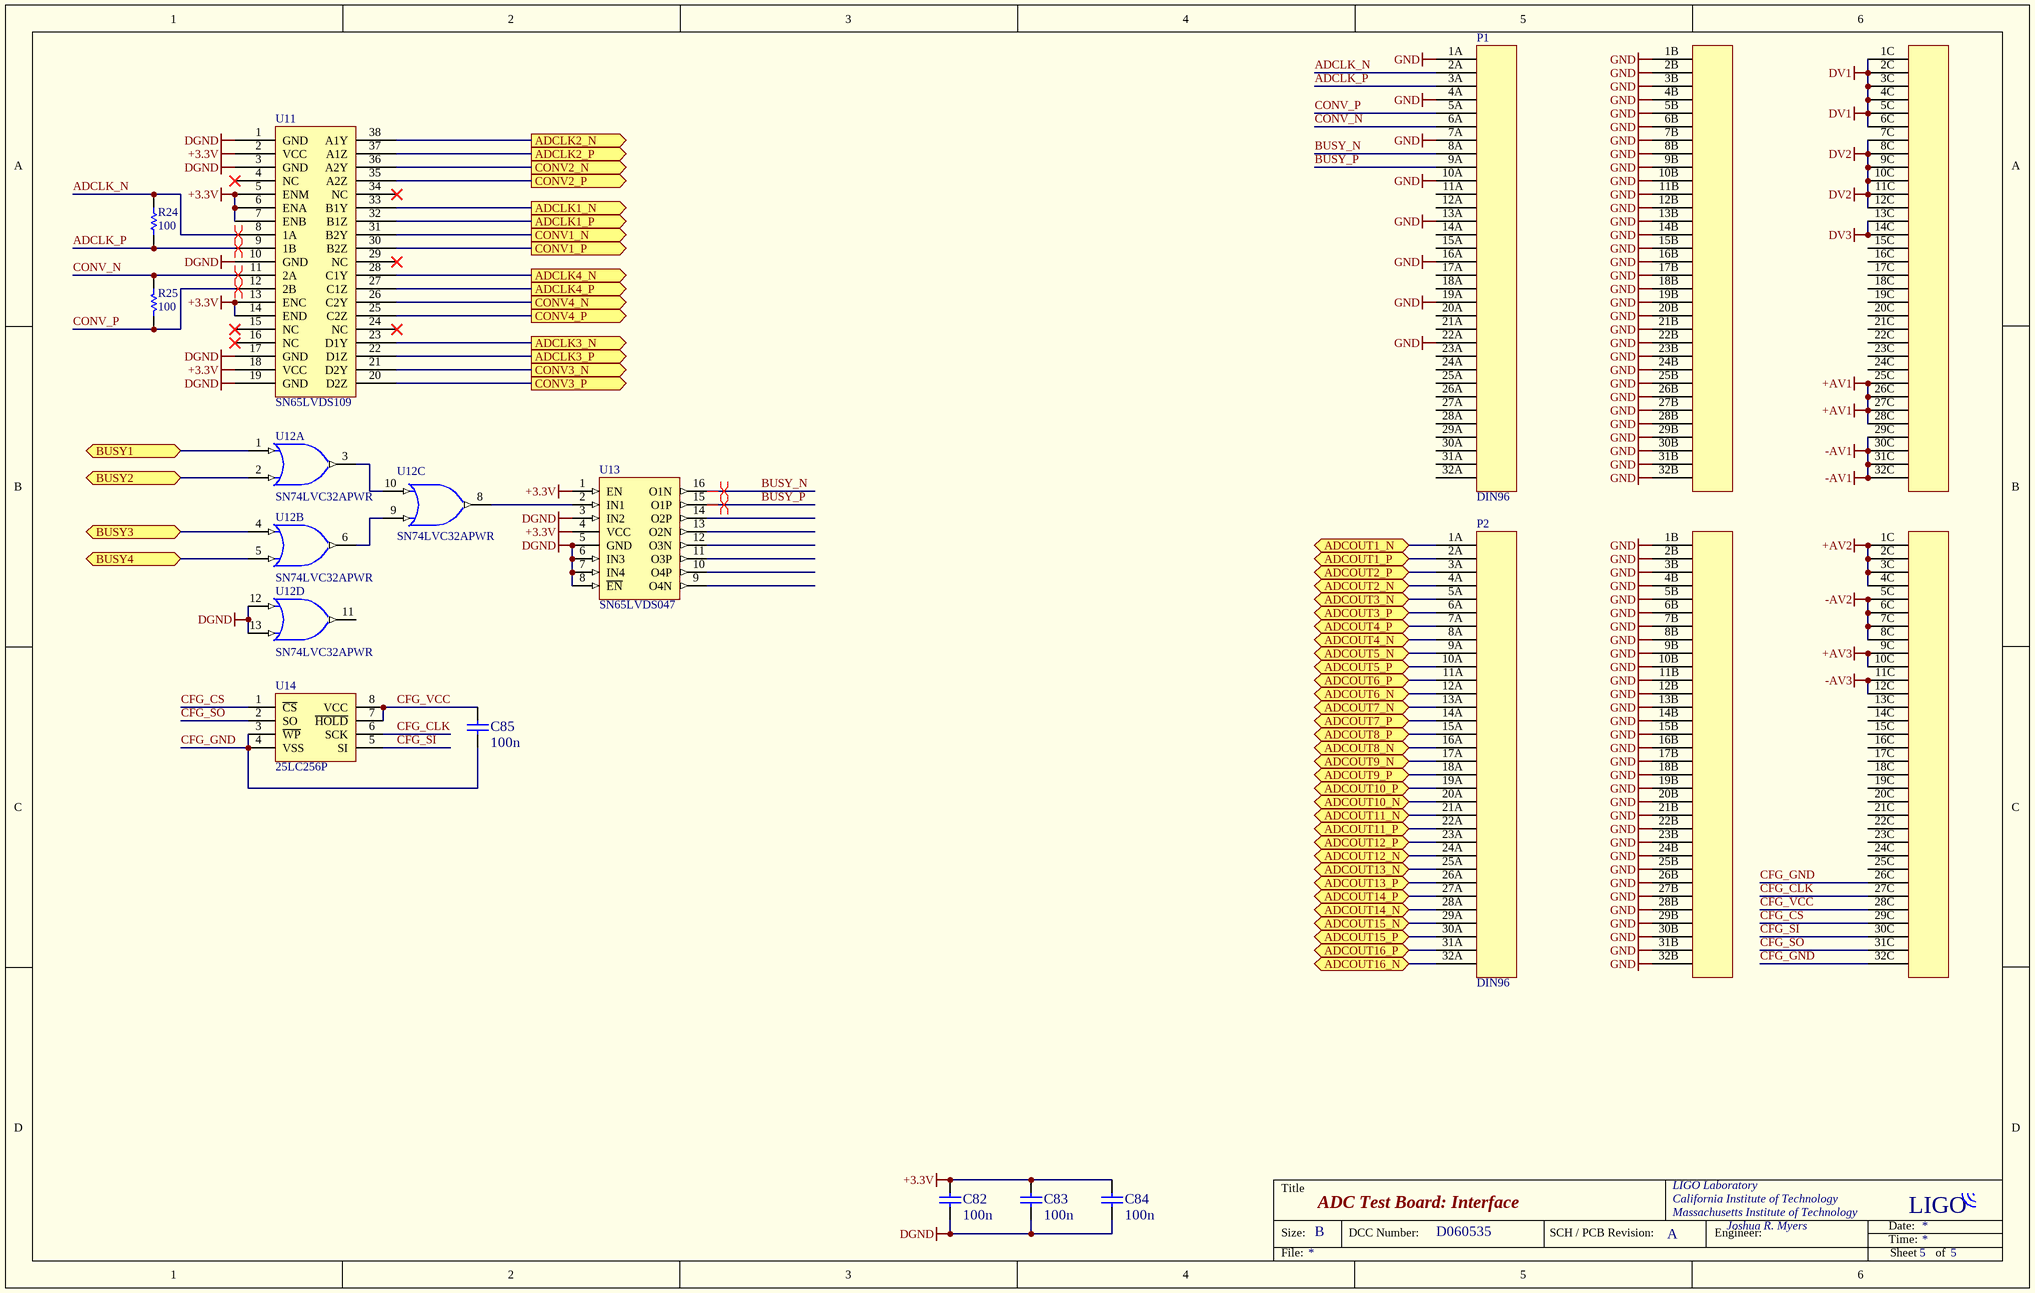
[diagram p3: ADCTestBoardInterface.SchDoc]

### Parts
C82  100n  [CC2013-0805]
C83  100n  [CC2013-0805]
C84  100n  [CC2013-0805]
C85  100n  [CC2013-0805]
P1  DIN96  [DIN96RA]
P2  DIN96  [DIN96RA]
R24  100  [CR2012-0805]
R25  100  [CR2012-0805]
U11  SN65LVDS109  [TSSO10x6-G38]
U12  SN74LVC32APWR  [PW014]  (parts A,B,C,D of 4)
U13  SN65LVDS047  [SO-G16]
U14  25LC256P  [DIP8]

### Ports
ADCLK1_N, ADCLK1_P, ADCLK2_N, ADCLK2_P, ADCLK3_N, ADCLK3_P, ADCLK4_N, ADCLK4_P, ADCOUT1_N, ADCOUT1_P, ADCOUT2_N, ADCOUT2_P, ADCOUT3_N, ADCOUT3_P, ADCOUT4_N, ADCOUT4_P, ADCOUT5_N, ADCOUT5_P, ADCOUT6_N, ADCOUT6_P, ADCOUT7_N, ADCOUT7_P, ADCOUT8_N, ADCOUT8_P, ADCOUT9_N, ADCOUT9_P, ADCOUT10_N, ADCOUT10_P, ADCOUT11_N, ADCOUT11_P, ADCOUT12_N, ADCOUT12_P, ADCOUT13_N, ADCOUT13_P, ADCOUT14_N, ADCOUT14_P, ADCOUT15_N, ADCOUT15_P, ADCOUT16_N, ADCOUT16_P, BUSY1, BUSY2, BUSY3, BUSY4, CONV1_N, CONV1_P, CONV2_N, CONV2_P, CONV3_N, CONV3_P, CONV4_N, CONV4_P

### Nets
+3.3V: C82.1 C83.1 C84.1 U11.2(VCC) U11.5(ENM) U11.6(ENA) U11.7(ENB) U11.13(ENC) U11.14(END) U11.18(VCC) U12.14(+3.3V) U13.1(EN) U13.4(VCC)
+AV1: P1.25C P1.26C P1.27C P1.28C
+AV2: P2.1C P2.2C P2.3C P2.4C
+AV3: P2.9C P2.10C
-AV1: P1.29C P1.30C P1.31C P1.32C
-AV2: P2.5C P2.6C P2.7C P2.8C
-AV3: P2.11C P2.12C
DGND: C82.2 C83.2 C84.2 U11.1(GND) U11.3(GND) U11.10(GND) U11.17(GND) U11.19(GND) U12.7(DGND) U12.12(A) U12.13(B) U13.3(IN2) U13.5(GND) U13.6(IN3) U13.7(IN4) U13.8(~{EN})
DV1: P1.1C P1.2C P1.3C P1.4C P1.5C P1.6C
DV2: P1.7C P1.8C P1.9C P1.10C P1.11C P1.12C
DV3: P1.13C P1.14C
GND: P1.1A P1.1B P1.2B P1.3B P1.4A P1.4B P1.5B P1.6B P1.7A P1.7B P1.8B P1.9B P1.10A P1.10B P1.11B P1.12B P1.13A P1.13B P1.14B P1.15B P1.16A P1.16B P1.17B P1.18B P1.19A P1.19B P1.20B P1.21B P1.22A P1.22B P1.23B P1.24B P1.25B P1.26B P1.27B P1.28B P1.29B P1.30B P1.31B P1.32B P2.1B P2.2B P2.3B P2.4B P2.5B P2.6B P2.7B P2.8B P2.9B P2.10B P2.11B P2.12B P2.13B P2.14B P2.15B P2.16B P2.17B P2.18B P2.19B P2.20B P2.21B P2.22B P2.23B P2.24B P2.25B P2.26B P2.27B P2.28B P2.29B P2.30B P2.31B P2.32B
ADCLK1_N: U11.33(B1Y) ; port ADCLK1_N
ADCLK1_P: U11.32(B1Z) ; port ADCLK1_P
ADCLK2_N: U11.38(A1Y) ; port ADCLK2_N
ADCLK2_P: U11.37(A1Z) ; port ADCLK2_P
ADCLK3_N: U11.23(D1Y) ; port ADCLK3_N
ADCLK3_P: U11.22(D1Z) ; port ADCLK3_P
ADCLK4_N: U11.28(C1Y) ; port ADCLK4_N
ADCLK4_P: U11.27(C1Z) ; port ADCLK4_P
ADCLK_N: P1.2A R24.1 U11.8(1A)
ADCLK_P: P1.3A R24.2 U11.9(1B)
ADCOUT1_N: P2.1A ; port ADCOUT1_N
ADCOUT1_P: P2.2A ; port ADCOUT1_P
ADCOUT2_N: P2.4A ; port ADCOUT2_N
ADCOUT2_P: P2.3A ; port ADCOUT2_P
ADCOUT3_N: P2.5A ; port ADCOUT3_N
ADCOUT3_P: P2.6A ; port ADCOUT3_P
ADCOUT4_N: P2.8A ; port ADCOUT4_N
ADCOUT4_P: P2.7A ; port ADCOUT4_P
ADCOUT5_N: P2.9A ; port ADCOUT5_N
ADCOUT5_P: P2.10A ; port ADCOUT5_P
ADCOUT6_N: P2.12A ; port ADCOUT6_N
ADCOUT6_P: P2.11A ; port ADCOUT6_P
ADCOUT7_N: P2.13A ; port ADCOUT7_N
ADCOUT7_P: P2.14A ; port ADCOUT7_P
ADCOUT8_N: P2.16A ; port ADCOUT8_N
ADCOUT8_P: P2.15A ; port ADCOUT8_P
ADCOUT9_N: P2.17A ; port ADCOUT9_N
ADCOUT9_P: P2.18A ; port ADCOUT9_P
ADCOUT10_N: P2.20A ; port ADCOUT10_N
ADCOUT10_P: P2.19A ; port ADCOUT10_P
ADCOUT11_N: P2.21A ; port ADCOUT11_N
ADCOUT11_P: P2.22A ; port ADCOUT11_P
ADCOUT12_N: P2.24A ; port ADCOUT12_N
ADCOUT12_P: P2.23A ; port ADCOUT12_P
ADCOUT13_N: P2.25A ; port ADCOUT13_N
ADCOUT13_P: P2.26A ; port ADCOUT13_P
ADCOUT14_N: P2.28A ; port ADCOUT14_N
ADCOUT14_P: P2.27A ; port ADCOUT14_P
ADCOUT15_N: P2.29A ; port ADCOUT15_N
ADCOUT15_P: P2.30A ; port ADCOUT15_P
ADCOUT16_N: P2.32A ; port ADCOUT16_N
ADCOUT16_P: P2.31A ; port ADCOUT16_P
BUSY1: U12.1(A) ; port BUSY1
BUSY2: U12.2(B) ; port BUSY2
BUSY3: U12.4(A) ; port BUSY3
BUSY4: U12.5(B) ; port BUSY4
BUSY_N: P1.8A U13.16(O1N)
BUSY_P: P1.9A U13.15(O1P)
CFG_CLK: P2.27C U14.6(SCK)
CFG_CS: P2.29C U14.1(~{CS})
CFG_GND: C85.2 P2.26C P2.32C U14.3(~{WP}) U14.4(VSS)
CFG_SI: P2.30C U14.5(SI)
CFG_SO: P2.31C U14.2(SO)
CFG_VCC: C85.1 P2.28C U14.7(~{HOLD}) U14.8(VCC)
CONV1_N: U11.31(B2Y) ; port CONV1_N
CONV1_P: U11.30(B2Z) ; port CONV1_P
CONV2_N: U11.36(A2Y) ; port CONV2_N
CONV2_P: U11.35(A2Z) ; port CONV2_P
CONV3_N: U11.21(D2Y) ; port CONV3_N
CONV3_P: U11.20(D2Z) ; port CONV3_P
CONV4_N: U11.26(C2Y) ; port CONV4_N
CONV4_P: U11.25(C2Z) ; port CONV4_P
CONV_N: P1.6A R25.2 U11.11(2A)
CONV_P: P1.5A R25.1 U11.12(2B)
NetU12_3: U12.3(Y) U12.10(B)
NetU12_6: U12.6(Y) U12.9(A)
NetU12_8: U12.8(Y) U13.2(IN1)

Not connected (* = marked no-connect by the designer): P1 11A 12A 14A 15A 15C 16C 17A 17C 18A 18C 19C 20A 20C 21A 21C 22C 23A 23C 24A 24C 25A 26A 27A 28A 29A 30A 31A 32A; P2 13C 14C 15C 16C 17C 18C 19C 20C 21C 22C 23C 24C 25C; U11 4(NC)* 15(NC)* 16(NC)* 24(NC)* 29(NC)* 34(NC)*; U12 11(Y); U13 9(O4N) 10(O4P) 11(O3P) 12(O3N) 13(O2N) 14(O2P)

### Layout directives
differential pair: ADCLK_N, ADCLK_P, BUSY_N, BUSY_P, CONV_N, CONV_P

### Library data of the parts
C82-C85 = Cap Semi: as C43 on sheet ADCTB_QuadADC
P1 P2 = DIN96: DIN 96; Part Number: A29011-ND
R24 R25 = Res1: as R22 on sheet ADCTB_QuadADC
U11 = SN65LVDS109: Dual 4 Port LVDS Repeater; Part Number: 296-2347-5-ND
U12 = SN74LVC32AD: as U10 on sheet ADCTB_QuadADC
U13 = SN65LVDS047: LVDS DRIVER; Part Number: 296-6909-5-ND
U14 = 256K Serial EEPROM: Part Number: 25LC256-I/P-ND

## Sheet ADCTestBoardPower.SchDoc: ADC Test Board: Power
size B; Organization: LIGO Laboratory; Address1: California Institute of Technology; Address2: Massachusetts Institute of Technology; Address3: Joshua R. Myers; DocumentNumber: D060535; Revision: A; SheetNumber: 4; SheetTotal: 5; Engineer: Joshua R. Myers
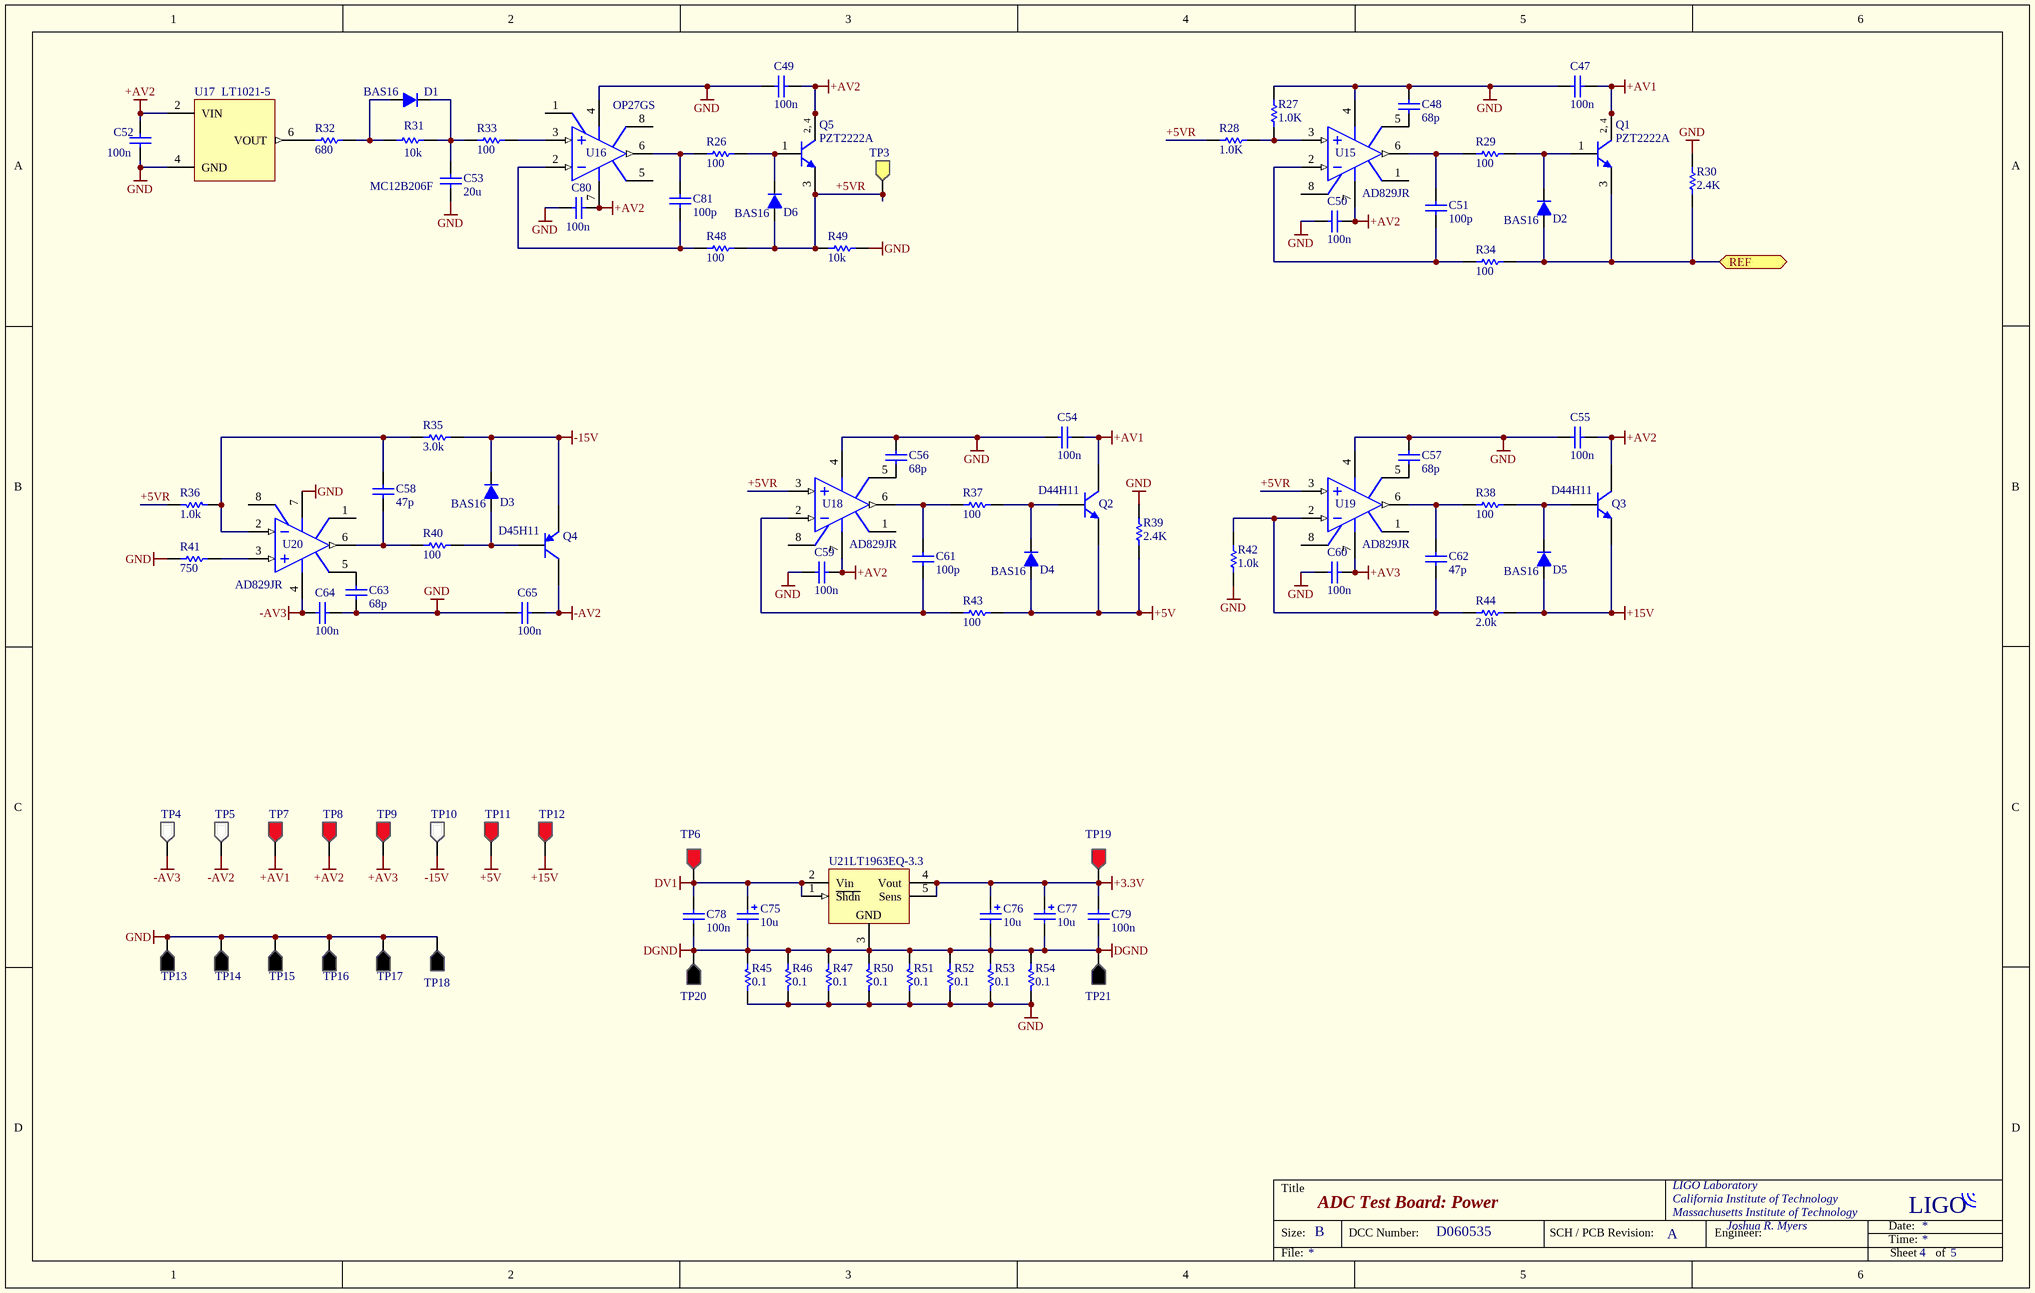
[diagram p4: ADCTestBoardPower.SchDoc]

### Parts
C47  100n  [CC2013-0805]
C48  68p  [CC2013-0805]
C49  100n  [CC2013-0805]
C50  100n  [CC2013-0805]
C51  100p  [CC2013-0805]
C52  100n  [CC2013-0805]
C53  Part Number: MC12B206F  [AXIAL1.7]  (hidden comment: 20u)
C54  100n  [CC2013-0805]
C55  100n  [CC2013-0805]
C56  68p  [CC2013-0805]
C57  68p  [CC2013-0805]
C58  47p  [CC2013-0805]
C59  100n  [CC2013-0805]
C60  100n  [CC2013-0805]
C61  100p  [CC2013-0805]
C62  47p  [CC2013-0805]
C63  68p  [CC2013-0805]
C64  100n  [CC2013-0805]
C65  100n  [CC2013-0805]
C75  10u  [TC3216-1206]
C76  10u  [TC3216-1206]
C77  10u  [TC3216-1206]
C78  100n  [CC2013-0805]
C79  100n  [CC2013-0805]
C80  100n  [CC2013-0805]
C81  100p  [CC2013-0805]
D1  BAS16  [SO-G3/C2.25]
D2  BAS16  [SO-G3/C2.25]
D3  BAS16  [SO-G3/C2.25]
D4  BAS16  [SO-G3/C2.25]
D5  BAS16  [SO-G3/C2.25]
D6  BAS16  [SO-G3/C2.25]
Q1  PZT2222A  [SOT223]
Q2  D44H11  [TO-220H+HS]
Q3  D44H11  [TO-220H+HS]
Q4  D45H11  [TO-220H+HS]
Q5  PZT2222A  [SOT223]
R26  100  [CR2012-0805]
R27  1.0K  [CR2012-0805]
R28  1.0K  [CR2012-0805]
R29  100  [CR2012-0805]
R30  2.4K  [CR2012-0805]
R31  10k  [CR2012-0805]
R32  680  [CR2012-0805]
R33  100  [CR2012-0805]
R34  100  [CR2012-0805]
R35  3.0k  [CR2012-0805]
R36  1.0k  [CR2012-0805]
R37  100  [CR2012-0805]
R38  100  [CR2012-0805]
R39  2.4K  [CR2012-0805]
R40  100  [CR2012-0805]
R41  750  [CR2012-0805]
R42  1.0k  [CR2012-0805]
R43  100  [CR2012-0805]
R44  2.0k  [CR2012-0805]
R45  0.1  [CR2012-0805]
R46  0.1  [CR2012-0805]
R47  0.1  [CR2012-0805]
R48  100  [CR2012-0805]
R49  10k  [CR2012-0805]
R50  0.1  [CR2012-0805]
R51  0.1  [CR2012-0805]
R52  0.1  [CR2012-0805]
R53  0.1  [CR2012-0805]
R54  0.1  [CR2012-0805]
TP3  Testpoint  [TP1]  (value not drawn)
TP4  -AV3  [TP1]  (value not drawn)
TP5  -AV2  [TP1]  (value not drawn)
TP6  DV1  [TP1]  (value not drawn)
TP7  +AV1  [TP1]  (value not drawn)
TP8  +AV2  [TP1]  (value not drawn)
TP9  +AV3  [TP1]  (value not drawn)
TP10  -15V  [TP1]  (value not drawn)
TP11  +5V  [TP1]  (value not drawn)
TP12  +15V  [TP1]  (value not drawn)
TP13  GND  [TP1]  (value not drawn)
TP14  GND  [TP1]  (value not drawn)
TP15  GND  [TP1]  (value not drawn)
TP16  GND  [TP1]  (value not drawn)
TP17  GND  [TP1]  (value not drawn)
TP18  GND  [TP1]  (value not drawn)
TP19  +3.3V  [TP1]  (value not drawn)
TP20  DGND  [TP1]  (value not drawn)
TP21  DGND  [TP1]  (value not drawn)
U15  AD829JR  [R-8D_N]
U16  OP27GS  [R-8D_N]
U17  LT1021-5  [N8]
U18  AD829JR  [R-8D_N]
U19  AD829JR  [R-8D_N]
U20  AD829JR  [R-8D_N]
U21  LT1963EQ-3.3  [TO-263]

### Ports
REF

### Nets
+3.3V: C76.1 C77.1 C79.2 TP19.1 U21.4(Vout) U21.5(Sens)
+5V: D4.1(A) Q2.3(E) R39.2 R43.1 TP11.1
+15V: D5.1(A) Q3.3(E) R44.2 TP12.1
+AV1: C47.2 C54.2 Q1.2(C) Q1.4(C) Q2.2(C) TP7.1
+AV2: C49.1 C50.2 C52.2 C55.1 C59.2 C80.2 Q3.2(C) Q5.2(C) Q5.4(C) TP8.1 U15.7(V+) U16.7(V+) U17.2(VIN) U18.7(V+)
+AV3: C60.1 TP9.1 U19.7(V+)
-15V: D3.3(K) Q4.3(E) R35.2 TP10.1
-AV2: C65.1 Q4.2(C) TP5.1
-AV3: C64.2 TP4.1 U20.4(V-)
DGND: C75.2 C76.2 C77.2 C78.1 C79.1 R45.2 R46.2 R47.2 R50.2 R51.2 R52.2 R53.2 R54.2 TP20.1 TP21.1 U21.3(GND)
DV1: C75.1 C78.2 TP6.1 U21.1(~{Shdn}) U21.2(Vin)
GND: C47.1 C48.2 C49.2 C50.1 C52.1 C53.2 C54.1 C55.2 C56.2 C57.2 C59.1 C60.2 C63.1 C64.1 C65.2 C80.1 R27.2 R30.1 R39.1 R41.1 R42.1 R45.1 R46.1 R47.1 R49.1 R50.1 R51.1 R52.1 R53.1 R54.1 TP13.1 TP14.1 TP15.1 TP16.1 TP17.1 TP18.1 U15.4(V-) U16.4(V-) U17.4(GND) U18.4(V-) U19.4(V-) U20.7(V+)
+5VR: D6.1(A) Q5.3(E) R28.1 R36.2 R48.2 R49.2 TP3.1 U18.3(IN+) U19.3(IN+)
REF: D2.1(A) Q1.3(E) R30.2 R34.1 ; port REF
NetC48_1: C48.1 U15.5(C_COMP)
NetC51_1: C51.1 R34.2 U15.2(IN-)
NetC51_2: C51.2 R29.2 U15.6(OUT)
NetC53_1: C53.1 D1.3(K) R31.2 R33.1
NetC56_1: C56.1 U18.5(C_COMP)
NetC57_1: C57.1 U19.5(C_COMP)
NetC58_1: C58.1 R40.1 U20.6(OUT)
NetC58_2: C58.2 R35.1 R36.1 U20.2(IN-)
NetC61_1: C61.1 R43.2 U18.2(IN-)
NetC61_2: C61.2 R37.2 U18.6(OUT)
NetC62_1: C62.1 R42.2 R44.1 U19.2(IN-)
NetC62_2: C62.2 R38.1 U19.6(OUT)
NetC63_2: C63.2 U20.5(C_COMP)
NetC81_1: C81.1 R48.1 U16.2(IN-)
NetC81_2: C81.2 R26.1 U16.6(OUT)
NetD1_1: D1.1(A) R31.1 R32.2
NetD2_3: D2.3(K) Q1.1(B) R29.1
NetD3_1: D3.1(A) Q4.1(B) R40.2
NetD4_3: D4.3(K) Q2.1(B) R37.1
NetD5_3: D5.3(K) Q3.1(B) R38.2
NetD6_3: D6.3(K) Q5.1(B) R26.2
NetR27_1: R27.1 R28.2 U15.3(IN+)
NetR32_1: R32.1 U17.6(VOUT)
NetR33_2: R33.2 U16.3(IN+)
NetR41_2: R41.2 U20.3(IN+)

Not connected (* = marked no-connect by the designer): D1 2; D2 2; D3 2; D4 2; D5 2; D6 2; U15 1(OS_NUL) 8(OS_NUL); U16 1(CMPEN) 5(NC) 8(CMPEN); U17 1(DNC) 3(DNC) 5(DNC) 7(DNC) 8(DNC); U18 1(OS_NUL) 8(OS_NUL); U19 1(OS_NUL) 8(OS_NUL); U20 1(OS_NUL) 8(OS_NUL)

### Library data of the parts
C47 C49 C50 C52 C54 C55 C59 C60 C64 C65 C78-C80 = ChipCap: Capacitor, surface mount; Part Number: 478-1395-1-ND; Tolerance: 10%
C48 C56 C57 C63 = ChipCap: Capacitor, surface mount; Part Number: 311-1109-1-ND; Tolerance: 10%
C51 C61 C81 = ChipCap: Capacitor, surface mount; Part Number: 311-1111-1-ND; Tolerance: 10%
C53 = PolyCap: Polypropylene Film Capacitor, radial lead; Tolerance: 1%; Voltage Rating: 50V
C58 C62 = ChipCap: Capacitor, surface mount; Part Number: 311-1107-1-ND; Tolerance: 10%
C75-C77 = ChipTantalum: Tantalum capacitor, surface mount; Part Number: 511-1463-1-ND; Tolerance: 20%; Voltage Rating: 25V
D1-D6 = DIODE_SOT23: Single diode in SOT23 package; Part Number: BAS16FSCT-ND
Q1 Q5 = PZTA42: NPN High-voltage Transistor; Part Number: PZT2222ACT-ND
Q2 Q3 = D44H8: NPN Power Amplifier; Part Number: 497-2616-5-ND
Q4 = D45H8: PNP Power Amplifier; Part Number: D45H11-ND
R26 R29 R33 R34 R37 R38 R40 R43 R48 = ChipRes2: Resistor, surface mount; Part Number: 311-100CRCT-ND; Tolerance: 1%
R27 R28 R36 R42 = ChipRes2: Resistor, surface mount; Part Number: 311-1.00KCRCT-ND; Tolerance: 1%
R30 R39 = ChipRes2: Resistor, surface mount; Part Number: 311-2.40KCRCT-ND; Tolerance: 1%
R31 R49 = ChipRes2: Resistor, surface mount; Part Number: 311-10.0KCRCT-ND; Tolerance: 1%
R32 = ChipRes2: Resistor, surface mount; Part Number: 311-680CRCT-ND; Tolerance: 1%
R35 = ChipRes2: Resistor, surface mount; Part Number: 311-3.00KCRCT-ND; Tolerance: 1%
R41 = ChipRes2: Resistor, surface mount; Part Number: 311-750CRCT-ND; Tolerance: 1%
R44 = ChipRes2: Resistor, surface mount; Part Number: 311-2.00KCRCT-ND; Tolerance: 1%
R45-R47 R50-R54 = ChipRes2: Resistor, surface mount; Part Number: RL12S.10GCT-ND; Tolerance: 5%
TP3 = TP_SIGNAL: Testpoint, yellow; Part Number: 5009K-ND
TP4 TP5 TP10 = TP_NEGATIVE: Testpoint, white; Part Number: 5007K-ND
TP6-TP9 TP11 TP12 TP19 = TP_POSITIVE: Testpoint, red; Part Number: 5005K-ND
TP13-TP18 TP20 TP21 = TP_GND: Testpoint, black; Part Number: 5006K-ND
U15 U18-U20 = AD829JR: High-Speed, Low-Noise Video Operational Amplifier; Part Number: AD829JR-ND
U16 = OP27GS: Low-Noise, Precision Operational Amplifier; Part Number: OP27GS-ND; PackageDocument: revA; Note: Pin 5 is not connected.
U17 = LT1021-7: Voltage Ref; Part Number: LT1021BCN8-5-ND
U21 = LT1764A: 5 Terminal positive LDO regulator; Part Number: LT1963AEST-3.3-ND

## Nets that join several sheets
+3.3V: 1 (10 pins), 1/1 (C23_1.2 C24_1.2 C25_1.2 U6_1.18), 1/2 (C23_2.2 C24_2.2 C25_2.2 U6_2.18), 1/3 (C23_3.2 C24_3.2 C25_3.2 U6_3.18), 1/4 (C23_4.2 C24_4.2 C25_4.2 U6_4.18), 2 (10 pins), 2/1 (C23_5.2 C24_5.2 C25_5.2 U6_5.18), 2/2 (C23_6.2 C24_6.2 C25_6.2 U6_6.18), 2/3 (C23_7.2 C24_7.2 C25_7.2 U6_7.18), 2/4 (C23_8.2 C24_8.2 C25_8.2 U6_8.18), 3 (10 pins), 3/1 (C23_9.2 C24_9.2 C25_9.2 U6_9.18), 3/2 (C23_10.2 C24_10.2 C25_10.2 U6_10.18), 3/3 (C23_11.2 C24_11.2 C25_11.2 U6_11.18), 3/4 (C23_12.2 C24_12.2 C25_12.2 U6_12.18), ADCTestBoardInterface (13 pins), ADCTestBoardPower (6 pins), 4 (10 pins), 4/1 (C23_13.2 C24_13.2 C25_13.2 U6_13.18), 4/2 (C23_14.2 C24_14.2 C25_14.2 U6_14.18), 4/3 (C23_15.2 C24_15.2 C25_15.2 U6_15.18), 4/4 (C23_16.2 C24_16.2 C25_16.2 U6_16.18)
+5V: 1/1 (14 pins), 1/2 (14 pins), 1/3 (14 pins), 1/4 (14 pins), 2/1 (14 pins), 2/2 (14 pins), 2/3 (14 pins), 2/4 (14 pins), 3/1 (14 pins), 3/2 (14 pins), 3/3 (14 pins), 3/4 (14 pins), ADCTestBoardPower (5 pins), 4/1 (14 pins), 4/2 (14 pins), 4/3 (14 pins), 4/4 (14 pins)
+15V: 1/1 (14 pins), 1/2 (14 pins), 1/3 (14 pins), 1/4 (14 pins), 2/1 (14 pins), 2/2 (14 pins), 2/3 (14 pins), 2/4 (14 pins), 3/1 (14 pins), 3/2 (14 pins), 3/3 (14 pins), 3/4 (14 pins), ADCTestBoardPower (D5.1 Q3.3 R44.2 TP12.1), 4/1 (14 pins), 4/2 (14 pins), 4/3 (14 pins), 4/4 (14 pins)
+AV1: ADCTestBoardInterface (P1.25C P1.26C P1.27C P1.28C), ADCTestBoardPower (6 pins)
+AV2: ADCTestBoardInterface (P2.1C P2.2C P2.3C P2.4C), ADCTestBoardPower (14 pins)
+AV3: ADCTestBoardInterface (P2.9C P2.10C), ADCTestBoardPower (C60.1 TP9.1 U19.7)
-15V: 1/1 (14 pins), 1/2 (14 pins), 1/3 (14 pins), 1/4 (14 pins), 2/1 (14 pins), 2/2 (14 pins), 2/3 (14 pins), 2/4 (14 pins), 3/1 (14 pins), 3/2 (14 pins), 3/3 (14 pins), 3/4 (14 pins), ADCTestBoardPower (D3.3 Q4.3 R35.2 TP10.1), 4/1 (14 pins), 4/2 (14 pins), 4/3 (14 pins), 4/4 (14 pins)
-AV2: ADCTestBoardInterface (P2.5C P2.6C P2.7C P2.8C), ADCTestBoardPower (C65.1 Q4.2 TP5.1)
-AV3: ADCTestBoardInterface (P2.11C P2.12C), ADCTestBoardPower (C64.2 TP4.1 U20.4)
DGND: 1 (17 pins), 1/1 (12 pins), 1/2 (12 pins), 1/3 (12 pins), 1/4 (12 pins), 2 (17 pins), 2/1 (12 pins), 2/2 (12 pins), 2/3 (12 pins), 2/4 (12 pins), 3 (17 pins), 3/1 (12 pins), 3/2 (12 pins), 3/3 (12 pins), 3/4 (12 pins), ADCTestBoardInterface (16 pins), ADCTestBoardPower (16 pins), 4 (17 pins), 4/1 (12 pins), 4/2 (12 pins), 4/3 (12 pins), 4/4 (12 pins)
DV1: ADCTestBoardInterface (6 pins), ADCTestBoardPower (5 pins)
GND: ADCTB_Overview1 (16 pins), 1/1 (45 pins), 1/2 (45 pins), 1/3 (45 pins), 1/4 (45 pins), 2/1 (45 pins), 2/2 (45 pins), 2/3 (45 pins), 2/4 (45 pins), 3/1 (45 pins), 3/2 (45 pins), 3/3 (45 pins), 3/4 (45 pins), ADCTestBoardInterface (72 pins), ADCTestBoardPower (42 pins), 4/1 (45 pins), 4/2 (45 pins), 4/3 (45 pins), 4/4 (45 pins)
ADCLK1_N: 1 (R22_1.1 U7_1.1), ADCTestBoardInterface (U11.33)
ADCLK1_P: 1 (R22_1.2 U7_1.2), ADCTestBoardInterface (U11.32)
ADCLK2_N: 2 (R22_2.1 U7_2.1), ADCTestBoardInterface (U11.38)
ADCLK2_P: 2 (R22_2.2 U7_2.2), ADCTestBoardInterface (U11.37)
ADCLK3_N: 3 (R22_3.1 U7_3.1), ADCTestBoardInterface (U11.23)
ADCLK3_P: 3 (R22_3.2 U7_3.2), ADCTestBoardInterface (U11.22)
ADCLK4_N: ADCTestBoardInterface (U11.28), 4 (R22_4.1 U7_4.1)
ADCLK4_P: ADCTestBoardInterface (U11.27), 4 (R22_4.2 U7_4.2)
ADCOUT1_N: 1 (U9_1.16), ADCTestBoardInterface (P2.1A)
ADCOUT1_P: 1 (U9_1.15), ADCTestBoardInterface (P2.2A)
ADCOUT2_N: 1 (U9_1.13), ADCTestBoardInterface (P2.4A)
ADCOUT2_P: 1 (U9_1.14), ADCTestBoardInterface (P2.3A)
ADCOUT3_N: 1 (U9_1.12), ADCTestBoardInterface (P2.5A)
ADCOUT3_P: 1 (U9_1.11), ADCTestBoardInterface (P2.6A)
ADCOUT4_N: 1 (U9_1.9), ADCTestBoardInterface (P2.8A)
ADCOUT4_P: 1 (U9_1.10), ADCTestBoardInterface (P2.7A)
ADCOUT5_N: 2 (U9_2.16), ADCTestBoardInterface (P2.9A)
ADCOUT5_P: 2 (U9_2.15), ADCTestBoardInterface (P2.10A)
ADCOUT6_N: 2 (U9_2.13), ADCTestBoardInterface (P2.12A)
ADCOUT6_P: 2 (U9_2.14), ADCTestBoardInterface (P2.11A)
ADCOUT7_N: 2 (U9_2.12), ADCTestBoardInterface (P2.13A)
ADCOUT7_P: 2 (U9_2.11), ADCTestBoardInterface (P2.14A)
ADCOUT8_N: 2 (U9_2.9), ADCTestBoardInterface (P2.16A)
ADCOUT8_P: 2 (U9_2.10), ADCTestBoardInterface (P2.15A)
ADCOUT9_N: 3 (U9_3.16), ADCTestBoardInterface (P2.17A)
ADCOUT9_P: 3 (U9_3.15), ADCTestBoardInterface (P2.18A)
ADCOUT10_N: 3 (U9_3.13), ADCTestBoardInterface (P2.20A)
ADCOUT10_P: 3 (U9_3.14), ADCTestBoardInterface (P2.19A)
ADCOUT11_N: 3 (U9_3.12), ADCTestBoardInterface (P2.21A)
ADCOUT11_P: 3 (U9_3.11), ADCTestBoardInterface (P2.22A)
ADCOUT12_N: 3 (U9_3.9), ADCTestBoardInterface (P2.24A)
ADCOUT12_P: 3 (U9_3.10), ADCTestBoardInterface (P2.23A)
ADCOUT13_N: ADCTestBoardInterface (P2.25A), 4 (U9_4.16)
ADCOUT13_P: ADCTestBoardInterface (P2.26A), 4 (U9_4.15)
ADCOUT14_N: ADCTestBoardInterface (P2.28A), 4 (U9_4.13)
ADCOUT14_P: ADCTestBoardInterface (P2.27A), 4 (U9_4.14)
ADCOUT15_N: ADCTestBoardInterface (P2.29A), 4 (U9_4.12)
ADCOUT15_P: ADCTestBoardInterface (P2.30A), 4 (U9_4.11)
ADCOUT16_N: ADCTestBoardInterface (P2.32A), 4 (U9_4.9)
ADCOUT16_P: ADCTestBoardInterface (P2.31A), 4 (U9_4.10)
BUSY1: 1 (U10_1.8), ADCTestBoardInterface (U12.1)
BUSY2: 2 (U10_2.8), ADCTestBoardInterface (U12.2)
BUSY3: 3 (U10_3.8), ADCTestBoardInterface (U12.4)
BUSY4: ADCTestBoardInterface (U12.5), 4 (U10_4.8)
CONV1_N: 1 (R23_1.2 U7_1.3), ADCTestBoardInterface (U11.31)
CONV1_P: 1 (R23_1.1 U7_1.4), ADCTestBoardInterface (U11.30)
CONV2_N: 2 (R23_2.2 U7_2.3), ADCTestBoardInterface (U11.36)
CONV2_P: 2 (R23_2.1 U7_2.4), ADCTestBoardInterface (U11.35)
CONV3_N: 3 (R23_3.2 U7_3.3), ADCTestBoardInterface (U11.21)
CONV3_P: 3 (R23_3.1 U7_3.4), ADCTestBoardInterface (U11.20)
CONV4_N: ADCTestBoardInterface (U11.26), 4 (R23_4.2 U7_4.3)
CONV4_P: ADCTestBoardInterface (U11.25), 4 (R23_4.1 U7_4.4)
NetJ1_2: ADCTB_Overview1 (J1.2), 1/1 (R11_1.1 U2_1.3)
NetJ1_3: ADCTB_Overview1 (J1.3), 1/2 (R11_2.1 U2_2.3)
NetJ1_4: ADCTB_Overview1 (J1.4), 1/3 (R11_3.1 U2_3.3)
NetJ1_5: ADCTB_Overview1 (J1.5), 1/4 (R11_4.1 U2_4.3)
NetJ1_7: ADCTB_Overview1 (J1.7), 2/1 (R11_5.1 U2_5.3)
NetJ1_8: ADCTB_Overview1 (J1.8), 2/2 (R11_6.1 U2_6.3)
NetJ1_9: ADCTB_Overview1 (J1.9), 2/3 (R11_7.1 U2_7.3)
NetJ1_10: ADCTB_Overview1 (J1.10), 2/4 (R11_8.1 U2_8.3)
NetJ1_15: ADCTB_Overview1 (J1.15), 1/1 (R3_1.1 U1_1.3)
NetJ1_16: ADCTB_Overview1 (J1.16), 1/2 (R3_2.1 U1_2.3)
NetJ1_17: ADCTB_Overview1 (J1.17), 1/3 (R3_3.1 U1_3.3)
NetJ1_18: ADCTB_Overview1 (J1.18), 1/4 (R3_4.1 U1_4.3)
NetJ1_20: ADCTB_Overview1 (J1.20), 2/1 (R3_5.1 U1_5.3)
NetJ1_21: ADCTB_Overview1 (J1.21), 2/2 (R3_6.1 U1_6.3)
NetJ1_22: ADCTB_Overview1 (J1.22), 2/3 (R3_7.1 U1_7.3)
NetJ1_23: ADCTB_Overview1 (J1.23), 2/4 (R3_8.1 U1_8.3)
NetJ2_2: ADCTB_Overview1 (J2.2), 3/1 (R11_9.1 U2_9.3)
NetJ2_3: ADCTB_Overview1 (J2.3), 3/2 (R11_10.1 U2_10.3)
NetJ2_4: ADCTB_Overview1 (J2.4), 3/3 (R11_11.1 U2_11.3)
NetJ2_5: ADCTB_Overview1 (J2.5), 3/4 (R11_12.1 U2_12.3)
NetJ2_7: ADCTB_Overview1 (J2.7), 4/1 (R11_13.1 U2_13.3)
NetJ2_8: ADCTB_Overview1 (J2.8), 4/2 (R11_14.1 U2_14.3)
NetJ2_9: ADCTB_Overview1 (J2.9), 4/3 (R11_15.1 U2_15.3)
NetJ2_10: ADCTB_Overview1 (J2.10), 4/4 (R11_16.1 U2_16.3)
NetJ2_15: ADCTB_Overview1 (J2.15), 3/1 (R3_9.1 U1_9.3)
NetJ2_16: ADCTB_Overview1 (J2.16), 3/2 (R3_10.1 U1_10.3)
NetJ2_17: ADCTB_Overview1 (J2.17), 3/3 (R3_11.1 U1_11.3)
NetJ2_18: ADCTB_Overview1 (J2.18), 3/4 (R3_12.1 U1_12.3)
NetJ2_20: ADCTB_Overview1 (J2.20), 4/1 (R3_13.1 U1_13.3)
NetJ2_21: ADCTB_Overview1 (J2.21), 4/2 (R3_14.1 U1_14.3)
NetJ2_22: ADCTB_Overview1 (J2.22), 4/3 (R3_15.1 U1_15.3)
NetJ2_23: ADCTB_Overview1 (J2.23), 4/4 (R3_16.1 U1_16.3)
NetU6_1_21: 1 (U8_1.2), 1/1 (U6_1.21)
NetU6_1_22: 1 (U7_1.15 U8_1.11), 1/1 (U6_1.22), 1/2 (U6_2.22), 1/3 (U6_3.22), 1/4 (U6_4.22)
NetU6_1_29: 1 (U10_1.1), 1/1 (U6_1.29)
NetU6_1_35: 1 (U7_1.14), 1/1 (U6_1.35), 1/2 (U6_2.35), 1/3 (U6_3.35), 1/4 (U6_4.35)
NetU6_2_21: 1 (U8_1.3), 1/2 (U6_2.21)
NetU6_2_29: 1 (U10_1.2), 1/2 (U6_2.29)
NetU6_3_21: 1 (U8_1.4), 1/3 (U6_3.21)
NetU6_3_29: 1 (U10_1.4), 1/3 (U6_3.29)
NetU6_4_21: 1 (U8_1.5), 1/4 (U6_4.21)
NetU6_4_29: 1 (U10_1.5), 1/4 (U6_4.29)
NetU6_5_21: 2 (U8_2.2), 2/1 (U6_5.21)
NetU6_5_22: 2 (U7_2.15 U8_2.11), 2/1 (U6_5.22), 2/2 (U6_6.22), 2/3 (U6_7.22), 2/4 (U6_8.22)
NetU6_5_29: 2 (U10_2.1), 2/1 (U6_5.29)
NetU6_5_35: 2 (U7_2.14), 2/1 (U6_5.35), 2/2 (U6_6.35), 2/3 (U6_7.35), 2/4 (U6_8.35)
NetU6_6_21: 2 (U8_2.3), 2/2 (U6_6.21)
NetU6_6_29: 2 (U10_2.2), 2/2 (U6_6.29)
NetU6_7_21: 2 (U8_2.4), 2/3 (U6_7.21)
NetU6_7_29: 2 (U10_2.4), 2/3 (U6_7.29)
NetU6_8_21: 2 (U8_2.5), 2/4 (U6_8.21)
NetU6_8_29: 2 (U10_2.5), 2/4 (U6_8.29)
NetU6_9_21: 3 (U8_3.2), 3/1 (U6_9.21)
NetU6_9_22: 3 (U7_3.15 U8_3.11), 3/1 (U6_9.22), 3/2 (U6_10.22), 3/3 (U6_11.22), 3/4 (U6_12.22)
NetU6_9_29: 3 (U10_3.1), 3/1 (U6_9.29)
NetU6_9_35: 3 (U7_3.14), 3/1 (U6_9.35), 3/2 (U6_10.35), 3/3 (U6_11.35), 3/4 (U6_12.35)
NetU6_10_21: 3 (U8_3.3), 3/2 (U6_10.21)
NetU6_10_29: 3 (U10_3.2), 3/2 (U6_10.29)
NetU6_11_21: 3 (U8_3.4), 3/3 (U6_11.21)
NetU6_11_29: 3 (U10_3.4), 3/3 (U6_11.29)
NetU6_12_21: 3 (U8_3.5), 3/4 (U6_12.21)
NetU6_12_29: 3 (U10_3.5), 3/4 (U6_12.29)
NetU6_13_21: 4 (U8_4.2), 4/1 (U6_13.21)
NetU6_13_22: 4 (U7_4.15 U8_4.11), 4/1 (U6_13.22), 4/2 (U6_14.22), 4/3 (U6_15.22), 4/4 (U6_16.22)
NetU6_13_29: 4 (U10_4.1), 4/1 (U6_13.29)
NetU6_13_35: 4 (U7_4.14), 4/1 (U6_13.35), 4/2 (U6_14.35), 4/3 (U6_15.35), 4/4 (U6_16.35)
NetU6_14_21: 4 (U8_4.3), 4/2 (U6_14.21)
NetU6_14_29: 4 (U10_4.2), 4/2 (U6_14.29)
NetU6_15_21: 4 (U8_4.4), 4/3 (U6_15.21)
NetU6_15_29: 4 (U10_4.4), 4/3 (U6_15.29)
NetU6_16_21: 4 (U8_4.5), 4/4 (U6_16.21)
NetU6_16_29: 4 (U10_4.5), 4/4 (U6_16.29)
REF: 1/1 (C33_1.2 C35_1.1 U6_1.46), 1/2 (C33_2.2 C35_2.1 U6_2.46), 1/3 (C33_3.2 C35_3.1 U6_3.46), 1/4 (C33_4.2 C35_4.1 U6_4.46), 2/1 (C33_5.2 C35_5.1 U6_5.46), 2/2 (C33_6.2 C35_6.1 U6_6.46), 2/3 (C33_7.2 C35_7.1 U6_7.46), 2/4 (C33_8.2 C35_8.1 U6_8.46), 3/1 (C33_9.2 C35_9.1 U6_9.46), 3/2 (C33_10.2 C35_10.1 U6_10.46), 3/3 (C33_11.2 C35_11.1 U6_11.46), 3/4 (C33_12.2 C35_12.1 U6_12.46), ADCTestBoardPower (D2.1 Q1.3 R30.2 R34.1), 4/1 (C33_13.2 C35_13.1 U6_13.46), 4/2 (C33_14.2 C35_14.1 U6_14.46), 4/3 (C33_15.2 C35_15.1 U6_15.46), 4/4 (C33_16.2 C35_16.1 U6_16.46)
